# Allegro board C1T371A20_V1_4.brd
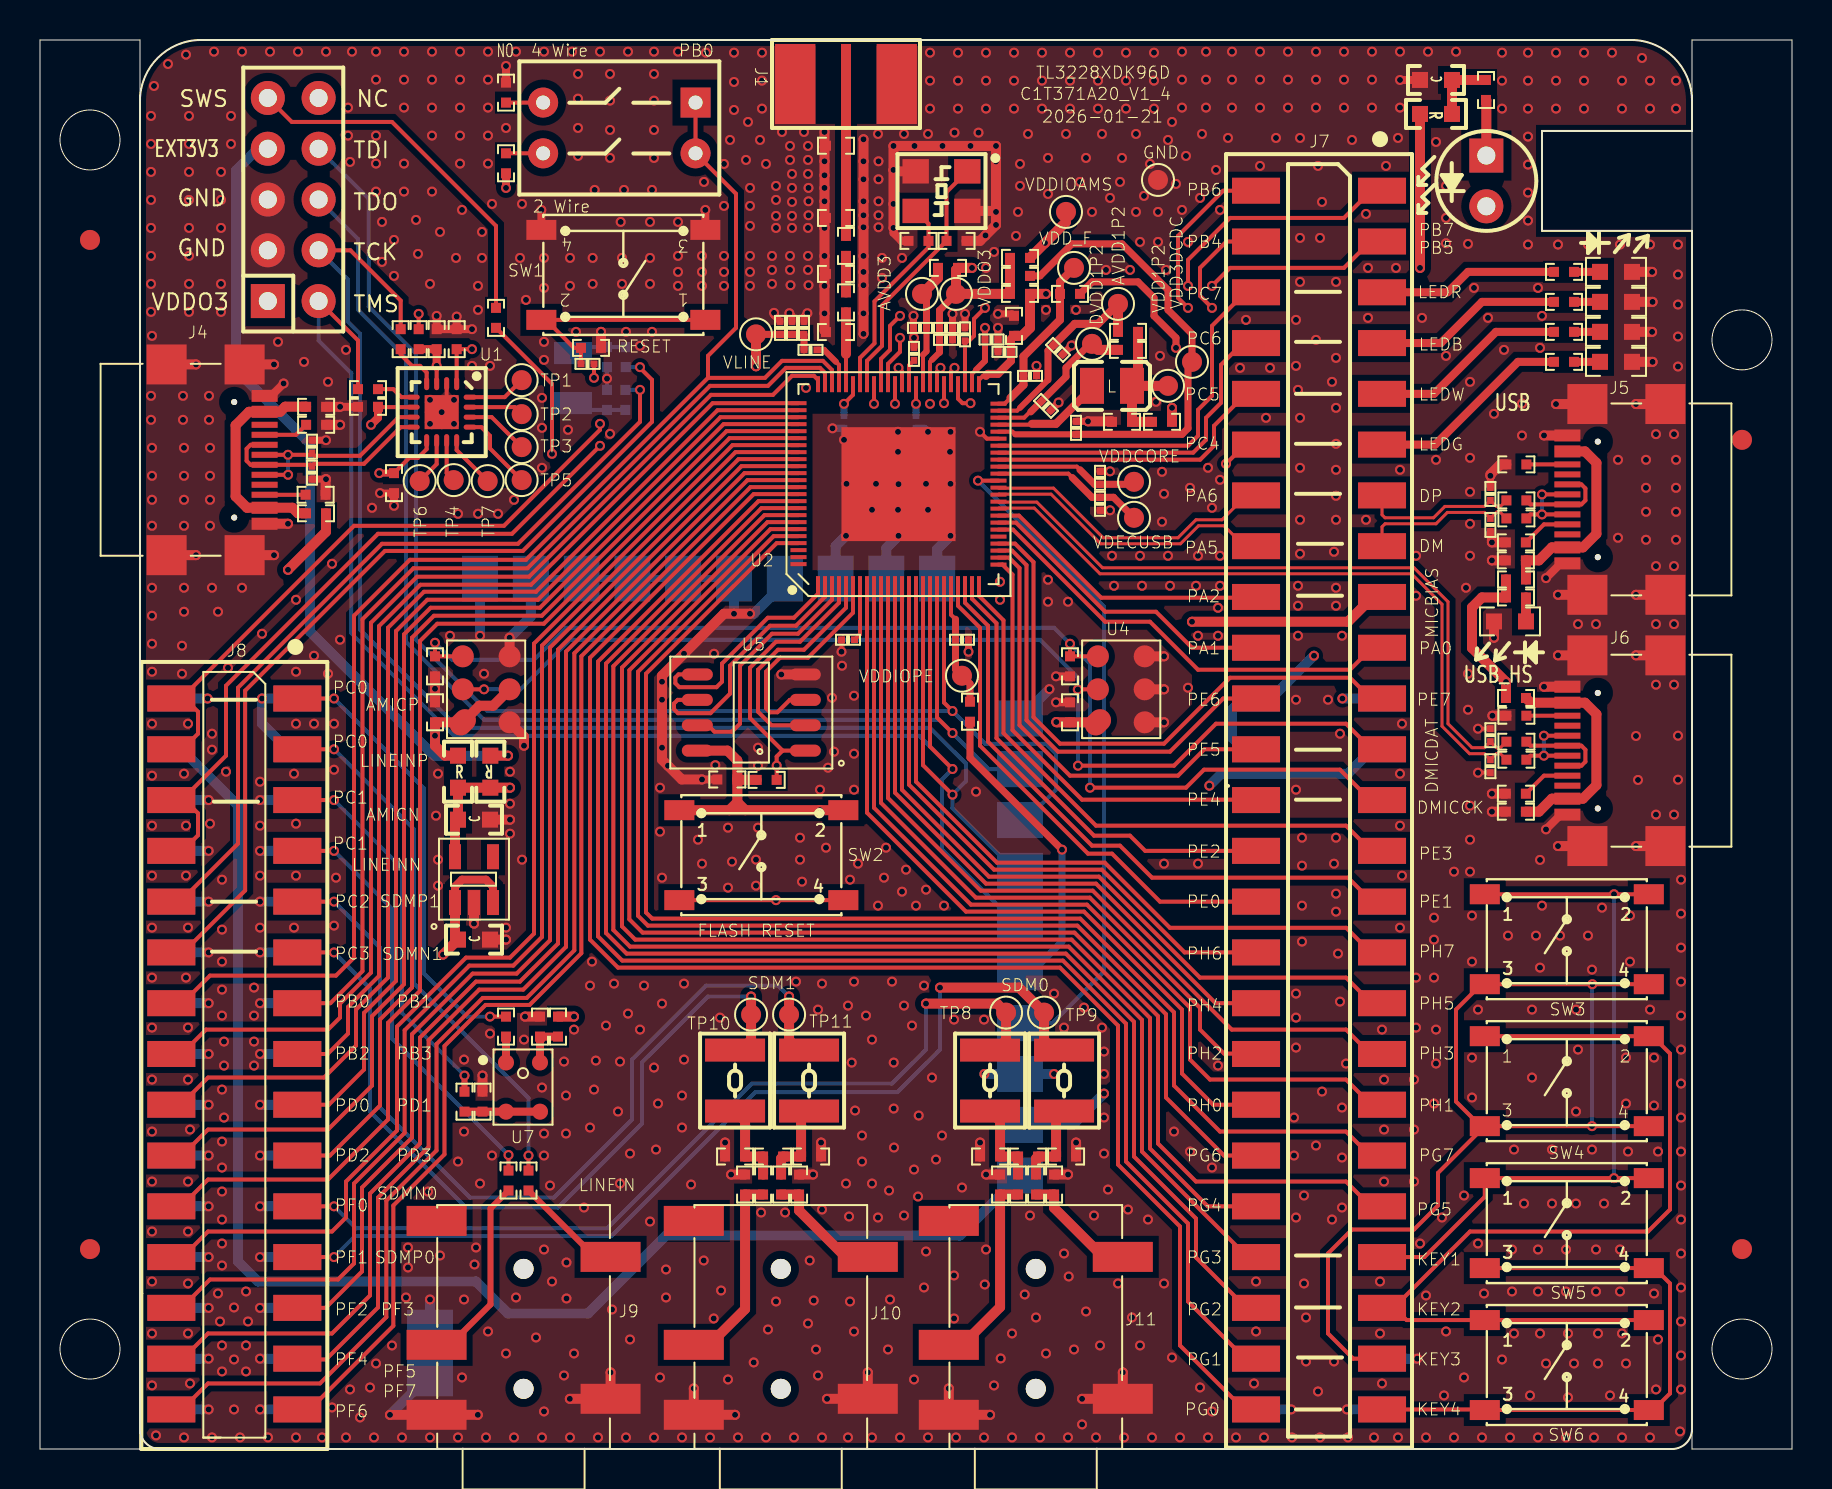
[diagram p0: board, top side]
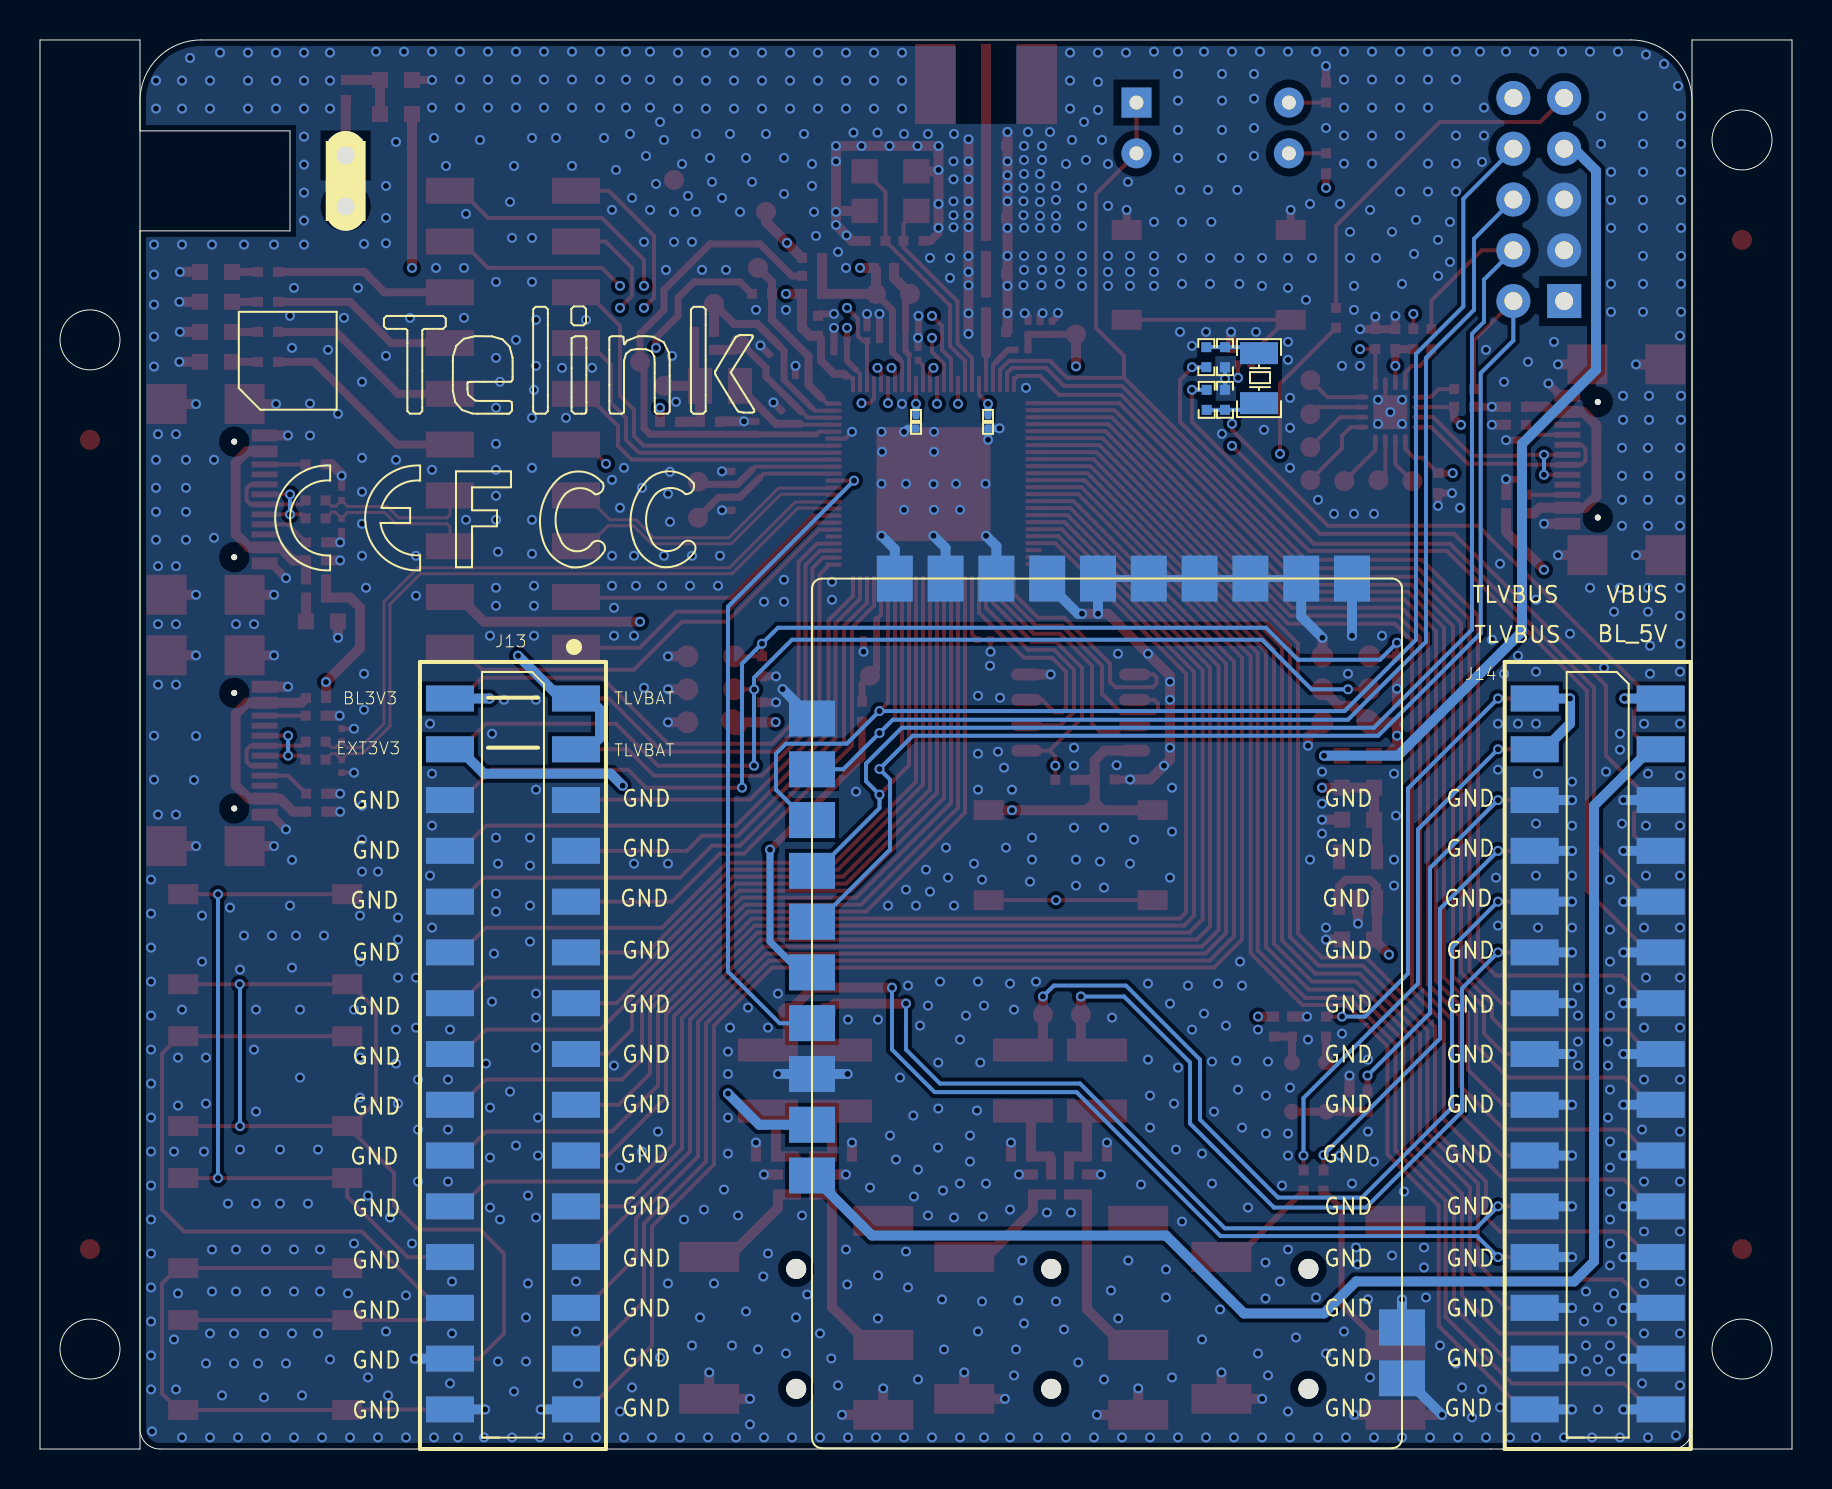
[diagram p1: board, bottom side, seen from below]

Outline 87.6 x 70.48 mm; copper layers: TOP, GND, POWER, BOTTOM. Coordinates in mm from the lower left corner of the outline.
Outline path: circle c2.5,65.48 r1.5 ; circle c2.5,5 r1.5 ; circle c85.1,55.48 r1.5 ; circle c85.1,5 r1.5 ; 0,70.48 5,70.48 5,0 0,0 0,70.48 ; 5,67.43 5,1 arc(5.29,0.29) 6,0 81.6,0 arc(82.31,0.29) 82.6,1 82.6,60.93 75.1,60.93 75.1,65.93 82.6,65.93 82.6,67.43 arc(81.71,69.59) 79.55,70.48 8.05,70.48 arc(5.89,69.59) 5,67.43 ; 82.6,70.48 87.6,70.48 87.6,0 82.6,0 82.6,70.48

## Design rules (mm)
net group DP1: nets TL_DM TL_DP
net group DP2: nets TL_PA3 TL_PA4
net group DP3: nets TL_PA5 TL_PA6
net group MG1: nets TL_MSPICK TL_MSPIIO2 TL_MSPIIO3 TL_MSPIMISO TL_MSPIMOSI

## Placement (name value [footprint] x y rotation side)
AVDD1P2  TP  [TP100]  53.9 57.28 0 top
AVDD3  TP  [TP100]  44.1 57.78 0 top
C1  10uF  [0603C]  69.8 68.48 0 top
C2  1.5pF  [0402]  39.8 61.58 0 top
C3  NC  [0402]  28.35 54.62 90 bottom
C4  NC  [0402]  28.35 52.48 270 bottom
C5  2.7pF  [0402]  39.8 58.78 0 top
C6  NC  [0402]  43.93 60.43 0 top
C7  NC  [0402]  45.83 60.43 180 top
C8  1.2pF  [0402]  39.8 55.87 0 top
C9  1uF  [0402]  27.55 55.08 0 top
C10  1uF  [0201]  43.7 54.78 90 top
C11  1uF  [0201]  44 56.08 180 top
C12  1uF  [0201]  45.3 56.08 0 top
C13  1uF  [0201]  47.58 55.5 0 top
C14  10uF  [0402]  48.7 56.18 90 top
C15  1uF  [0201]  49.5 53.68 0 top
C16  2.2uF  [0201]  37 56.08 90 top
C17  0.1uF  [0201]  37.6 56.08 90 top
C18  1uF  [0201]  50.9 54.98 315 top
C19  1uF  [0402]  19.83 55.51 90 top
C20  1uF  [0402]  20.83 55.51 90 top
C21  1uF  [0201]  50.3 52.18 315 top
C22  10uF  [0402]  54.1 51.38 180 top
C23  0.1uF  [0402]  16.4 52.13 180 top
C24  1uF  [0201]  51.8 51.08 90 top
C25  4.7uF  [0201]  53 48.58 90 top
C26  1uF  [0402]  17.7 48.31 270 top
C27  0.22uF  [0201]  53 47.28 270 top
C29  1uF  [0201]  40.4 40.48 180 top
C30  1uF  [0201]  46.1 40.48 0 top
C31  0.1uF  [0402]  19.75 36.85 90 top
C32  0.1uF  [0402]  51.5 36.85 90 top
C33  1uF  [0402]  34.37 33.49 180 top
C34  10uF  [0603C]  21.7 31.48 0 top
C35  10uF  [0603C]  21.7 25.48 0 top
C36  10nF  [0402]  23.3 21.13 90 top
C37  1uF  [0402]  25 21.13 90 top
C38  10nF  [0402]  21.22 17.38 90 top
C39  NC  [0402]  34.75 14.63 0 top
C40  220nF  [0402]  36.65 14.63 0 top
C41  NC  [0402]  38.55 14.63 0 top
C42  NC  [0402]  47.5 14.63 0 top
C43  220nF  [0402]  49.4 14.63 0 top
C44  NC  [0402]  51.3 14.63 0 top
C45  1uF  [0402]  23.43 13.43 90 top
C46  1uF  [0402]  24.43 13.43 90 top
C47  10pF  [0402]  35.25 13.23 270 top
C48  10pF  [0402]  37.95 13.23 90 top
C49  10pF  [0402]  48 13.23 270 top
C50  10pF  [0402]  50.7 13.23 90 top
C51  3.9pF  [0201]  38.2 56.08 90 top
C52  NC/3.9pF  [0201]  40.2 51.38 270 bottom
C53  3.9pF  [0201]  45.3 55.48 0 top
C56  3.9pF  [0201]  48.22 54.88 180 top
C61  NC/1uF  [0201]  43.8 51.38 270 bottom
C65  3.9pF  [0201]  46.25 55.76 90 top
D1  TT0321  [0402]  39.8 65.19 0 top
D2  LED_IR  [LED_TH_2P54MM_2PIN]  72.32 63.43 90 top
D3  Red  [0603-LED]  78.8 58.88 0 top
D4  Blue  [0603-LED]  78.8 57.38 0 top
D5  White  [0603-LED]  78.8 55.88 0 top
D6  Green  [0603-LED]  78.8 54.38 0 top
D7  NC  [0402]  13.81 52.13 180 top
D8  NC  [0201]  13.6 50.14 270 top
D9  NC  [0201]  13.6 48.84 90 top
D10  NC  [0201]  72.52 47.77 270 top
D11  NC  [0201]  72.52 46.22 90 top
D12  NC  [0402]  73.79 44.45 0 top
D13  Green  [0603-LED]  73.5 41.4 180 top
D14  NC  [0201]  72.52 35.71 270 top
D15  NC  [0201]  72.52 34.16 90 top
D16  NC  [0402]  73.79 31.88 0 top
DVDD1P2  TP  [TP100]  52.6 55.28 0 top
GND  TP  [TP100]  55.9 63.48 0 top
J1  RFIN  [SMA-H]  40.3 68.28 270 top
J2  DIP_2X2  [DIPSWITCH_2P54_7P62_2X2]  28.97 66.08 90 top
J3  JTAG  [HDR254F-2X5X850]  11.39 67.58 270 top
J4  Type-C 16pin  [TYPE_C_CQ_105PWB]  10.23 49.48 270 top
J5  Type-C 16pin  [TYPE_C_CQ_105PWB]  77.37 47.5 90 top
J6  Type-C 16pin  [TYPE_C_CQ_105PWB]  77.37 34.93 90 top
J7  HEADER 25X2  [HDR2X25-2R54-SM-M]  63.95 32.42 90 top
J8  HEADER 17X2  [SMD254M-2X15_RX1_30Y2_40]  9.72 10.87 90 top
J9  AIL1  [PJ-327]  24.18 0.01 180 top
J10  PJ327  [PJ-327]  37.04 0.01 180 top
J11  PJ327  [PJ-327]  49.79 0.01 180 top
J12  CON22  [ML_HDR254F-2X10X850]  49 13.68 90 bottom
J13  HEADER 17X2  [SMD254M-2X15_RX1_30Y2_40]  63.95 10.87 90 bottom
J14  HEADER 17X2  [SMD254M-2X15_RX1_30Y2_40]  9.72 10.87 90 bottom
L1  1.5nH  [0402]  40.3 60.18 90 top
L2  2.4nH  [0402]  40.3 57.36 90 top
L3  BEAD_600  [0402]  18.93 55.51 90 top
L4  6.8uH  [0806L]  53.6 53.18 0 top
L5  150uH  [INDM3025X25]  34.75 18.43 270 top
L6  150uH  [INDM3025X25]  38.45 18.43 270 top
L7  150uH  [INDM3025X25]  47.5 18.43 270 top
L8  150uH  [INDM3025X25]  51.2 18.43 270 top
L9  0  [0201]  38.53 54.98 180 top
L11  0  [0201]  27.38 54.28 180 top
NOREF  -  [unnamed]  2.5 60.48 180 top
NOREF#2  -  [unnamed]  85.1 50.48 180 top
NOREF#3  -  [unnamed]  85.1 10 0 top
NOREF#4  -  [unnamed]  2.5 10 0 top
R1  0  [0402]  22.8 56.58 270 top
R2  1R  [0402]  72.3 67.98 270 top
R3  1M  [0402]  23.3 67.85 90 top
R4  0R  [0603R]  69.8 66.78 180 top
R5  1K  [0402]  23.3 64.31 270 top
R6  NC  [0402]  29.27 52.48 90 bottom
R7  NC  [0402]  29.28 54.62 270 bottom
R8  1K  [0402]  76.2 58.88 0 top
R9  1K  [0402]  76.2 57.38 0 top
R10  1K  [0402]  76.2 55.88 0 top
R11  0R  [0402]  18.03 55.51 90 top
R12  1K  [0402]  76.2 54.38 0 top
R13  0R  [0402]  16.4 53.01 180 top
R14  5.1K  [0402]  13.81 51.23 180 top
R15  5.1K  [0402]  73.82 49.25 0 top
R16  5.1K  [0402]  13.78 47.73 180 top
R17  33  [0402]  73.82 47.45 180 top
R18  2R  [0402]  13.8 46.81 180 top
R19  33  [0402]  73.82 46.55 180 top
R20  5.1K  [0402]  73.79 45.35 0 top
R21  2R  [0402]  73.8 43.5 0 top
R22  10K  [0402]  73.8 42.6 180 top
R23  100K  [0402]  19.75 39.15 90 top
R24  100K  [0402]  51.5 39.15 90 top
R25  2R  [0402]  73.8 37.57 0 top
R26  5.1K  [0402]  73.82 36.68 0 top
R27  0  [0402]  73.82 35.38 180 top
R28  0  [0402]  73.82 34.48 180 top
R29  0R  [0603R]  20.9 33.88 270 top
R30  0R  [0603R]  22.52 33.88 90 top
R31  4.7K  [0402]  36.33 33.47 0 top
R32  5.1K  [0402]  73.79 32.78 0 top
R33  2.2K  [0402]  25.9 21.13 270 top
R34  2.2K  [0402]  22.12 17.38 270 top
R35  33  [0402R]  36.15 13.23 270 top
R36  33  [0402R]  37.05 13.23 270 top
R37  33  [0402R]  48.9 13.23 270 top
R38  33  [0402R]  49.8 13.23 270 top
R39  0  [0402R]  54.4 54.98 180 top
R40  0  [0402R]  54.4 55.88 180 top
R41  0  [0402R]  56.1 51.38 0 top
R42  0  [0402R]  49 59.58 0 top
R43  0  [0402R]  45.4 59.08 180 top
R44  0  [0402R]  49 58.68 0 top
R45  0  [0402R]  46.5 36.88 90 top
R46  0  [0402R]  51.5 57.78 0 top
R47  NC  [0402R]  49 57.78 0 top
SW1  SW4PIN_4.5x4.5  [SW_6X6_SMD]  29.17 58.73 180 top
SW2  FRST  [SW_6X6_SMD]  36.07 29.7 0 top
SW3  SW4PIN_4.5x4.5  [SW_6X6_SMD]  76.34 25.5 0 top
SW4  SW4PIN_4.5x4.5  [SW_6X6_SMD]  76.34 18.4 0 top
SW5  SW4PIN_4.5x4.5  [SW_6X6_SMD]  76.34 11.3 0 top
SW6  SW4PIN_4.5x4.5  [SW_6X6_SMD]  76.34 4.2 0 top
TP1  TP  [TP100]  24.08 53.46 270 top
TP2  TP  [TP100]  24.08 51.76 270 top
TP3  TP  [TP100]  24.08 50.11 270 top
TP4  TP  [TP100]  20.68 48.46 270 top
TP5  TP  [TP100]  24.08 48.46 270 top
TP6  TP  [TP100]  18.98 48.41 270 top
TP7  TP  [TP100]  22.38 48.41 270 top
TP8  B0  [TP100]  48.3 21.83 0 top
TP9  B1  [TP100]  50.2 21.83 0 top
TP10  D4  [TP100]  35.55 21.73 0 top
TP11  D5  [TP100]  37.45 21.73 0 top
U1  CH343P  [QFN_3X3_16PIN_0P5_1P70X1P70]  20.08 51.86 270 top
U2  TL3228X  [QFN_10X10_96PIN_0P35_5P7X5P7]  42.93 48.26 90 top
U3  WMM7047DTFN0  [DMIC_SPM0423HM4H-WB]  22.31 38 90 top
U4  WMM7047DTFN0  [DMIC_SPM0423HM4H-WB]  54.07 38 90 top
U5  P25Q32SU-SSH-IT  [W25X10_20_40BL]  35.57 36.84 90 top
U6  CE1132_3.3V_SOT-23-5  [SOT-23-5]  21.7 28.48 0 top
U7  WMM7037AT2  [GA_BFA423_A83]  24.15 18.11 0 top
VDD1P2  TP  [TP100]  56.4 53.18 0 top
VDD3DCDC  TP  [TP100]  57.6 54.38 0 top
VDD_F  TP  [TP100]  51.7 59.08 0 top
VDDCORE  TP  [TP100]  54.7 48.38 0 top
VDDIOAMS  TP  [TP100]  51.3 61.88 0 top
VDDIOPE  TP  [TP100]  46.1 38.68 0 top
VDDO3  TP  [TP100]  45.8 57.78 0 top
VDECUSB  TP  [TP100]  54.7 46.58 0 top
VLINE  TP  [TP100]  35.8 55.76 0 top
Y1  NC  [OSC-ABS07]  26.65 53.57 270 bottom
Y2  24MHz-12pF-+/-10ppm  [OSCCC250X320X110]  45.08 62.92 270 top

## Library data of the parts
AVDD1P2 AVDD3 DVDD1P2 GND TP1-TP11 VDD1P2 VDD3DCDC VDD_F VDDCORE VDDIOAMS VDDIOPE VDDO3 VDECUSB VLINE = TestPad100
C1 C9 C14 C22 C33 C36-C38 C45 C46 = C1005X5R1C104K
C2-C5 C8 = C1608_NC
C6 C7 C19 C20 C23 C26 C39 C41 C42 C44 = C1005_NC
C10-C13 C15-C18 C21 C24 C25 C27 C29 C30 C51-C53 C56 C61 C65 = C1005X5R1C104K: User Part Number: pn; Tolerance: RichardLC
C31 C32 = C1005X5R1C104K_1
C34 C35 = C1608X5R0J106M
C40 C43 = C1005X5R1C224M
C47-C50 = C1005C0G1H100D
D1 D7 D12 D16 = DIODE SCHOTTKY_0
D2 = Led_Th_3mm_1: User Part Number: partnum; Tolerance: RichardLC
D3-D6 D13 = 0603D_Green
D8-D11 D14 D15 = DIODE SCHOTTKY_0: User Part Number: pn; Tolerance: RichardLC
J1 = SMA_JACK_2
J2 = HEADER 2X2_0: Tolerance: RichardLC; User Part Number: pn
J3 = CONN PLUG 5x2: Tolerance: RichardLC; User Part Number: pn
J4-J6 = Type-C 16pin_0
J7 = HEADER 16X2_9: Tolerance: RichardLC
J8 J13 J14 = HEADER 16X2_13: Tolerance: RichardLC
J9-J11 = PJ327_2
J12 = CON24B_0: User Part Number: pn; Tolerance: RichardLC
L1 L2 = MLK1608_000R
L3 = MMZ1005Y601C
L4 = IND
L5-L8 = IND_150uH_3025
L9 L11 = MLK1608_000R: User Part Number: pn; Tolerance: RichardLC
R1 R3-R5 R23 R24 R29-R31 R33 R34 = RS0402K104JT
R2 R11 R13 R22 = RS0402K102JT
R6 R7 = RS0603K102JT
R8-R10 R12 = RS0402K101JT
R14-R21 R25-R28 R32 = RS0402K330JT: room: USB
R35-R47 = RS0402K330JT
SW1 SW3-SW6 = SW_6X6_SMD_0
SW2 = SW_6X6_SMD
U1 = CH343P
U2 = TL3228X_QFN96: Tolerance: RichardLC; User Part Number: pn
U3 = LD1117/SO_1
U4 = LD1117/SO_0
U5 = GD25LD40C_0: Tolerance: RichardLC
U6 = CE1132_1V8_SOT-23-5
U7 = MULPS4CX-RM5_0
Y1 = OSC_2x6_2pin_16Mhz
Y2 = CRYSTAL4/SM_0

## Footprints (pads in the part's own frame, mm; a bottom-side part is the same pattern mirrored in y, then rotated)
0201
  rect 0.35x0.33 smd: 1(-0.325,0) 2(0.325,0)
0402
  rect 0.5x0.5 smd: 1(-0.5,0) 2(0.5,0)
0402R
  rect 0.5x0.5 smd: 1(-0.5,0) 2(0.5,0)
0603-LED
  rect 0.8x0.8 smd: A(-0.8,0) C(0.8,0)
0603C
  rect 0.8x0.8 smd: 1(-0.8,0) 2(0.8,0)
0603R
  rect 0.8x0.8 smd: 1(-0.8,0) 2(0.8,0)
0806L
  rect 1.2x1.8 smd: 1(-1,0) 2(1,0)
DIPSWITCH_2P54_7P62_2X2
  rect 1.5x1.5 hole 0.7: 1(1.27,-3.81)
  round 1.5 hole 0.7: 2(1.27,3.81) 3(-1.27,-3.81) 4(-1.27,3.81)
DMIC_SPM0423HM4H-WB
  round 1.1 smd: 1(-1.65,-1.17) 2(0,-1.17) 3(1.65,-1.17) 4(1.65,1.17) 5(0,1.17)
  oval 1.4x1.1 smd rot 135: 6(-1.65,1.17)
GA_BFA423_A83
  round 0.8 smd: 1(-0.85,1.23) 2(-0.85,-1.23) 3(0.85,-1.23) 4(0.85,1.23)
HDR2X25-2R54-SM-M
  rect 1.3x2.4 smd: 1(30.52,-3.15) 2(30.52,3.15) 3(27.98,-3.15) 4(27.98,3.15) 5(25.44,-3.15) 6(25.44,3.15) 7(22.9,-3.15) 8(22.9,3.15) 9(20.36,-3.15) 10(20.36,3.15) 11(17.82,-3.15) 12(17.82,3.15) 13(15.28,-3.15) 14(15.28,3.15) 15(12.74,-3.15) 16(12.74,3.15) 17(10.2,-3.15) 18(10.2,3.15) 19(7.66,-3.15) 20(7.66,3.15) 21(5.12,-3.15) 22(5.12,3.15) 23(2.58,-3.15) 24(2.58,3.15) 25(0.04,-3.15) 26(0.04,3.15) 27(-2.5,-3.15) 28(-2.5,3.15) 29(-5.04,-3.15) 30(-5.04,3.15) 31(-7.58,-3.15) 32(-7.58,3.15) 33(-10.12,-3.15) 34(-10.12,3.15) 35(-12.66,-3.15) 36(-12.66,3.15) 37(-15.2,-3.15) 38(-15.2,3.15) 39(-17.74,-3.15) 40(-17.74,3.15) 41(-20.28,-3.15) 42(-20.28,3.15) 43(-22.82,-3.15) 44(-22.82,3.15) 45(-25.36,-3.15) 46(-25.36,3.15) 47(-27.9,-3.15) 48(-27.9,3.15) 49(-30.44,-3.15) 50(-30.44,3.15)
HDR254F-2X5X850
  rect 1.7x1.7 hole 0.9: 1(10.16,0)
  round 1.7 hole 0.9: 2(10.16,2.54) 3(7.62,0) 4(7.62,2.54) 5(5.08,0) 6(5.08,2.54) 7(2.54,0) 8(2.54,2.54) 9(0,0) 10(0,2.54)
INDM3025X25
  rect 1.15x3 smd: 1(-1.525,0) 2(1.525,0)
LED_TH_2P54MM_2PIN
  rect 1.7x1.7 hole 0.9: A(1.27,0)
  round 1.7 hole 0.9: C(-1.27,0)
ML_HDR254F-2X10X850
  rect 1.8x2.3 smd: 1(22.86,0) 2(20.32,0) 3(17.78,0) 4(15.24,0) 5(12.7,0) 6(10.16,0) 7(7.62,0) 8(5.08,0) 9(2.54,0) 10(0,0) 11(-10.14,-29.5) 12(-7.6,-29.5)
  rect 2.3x1.8 smd: 13(29.86,-27) 14(29.86,-24.46) 15(29.86,-21.92) 16(29.86,-19.38) 17(29.86,-16.84) 18(29.86,-14.3) 19(29.86,-11.76) 20(29.86,-9.22) 21(29.86,-6.68) 22(29.86,-4.14)
OSC-ABS07
  rect 1.1x1.9 smd: 1(-1.25,0) 2(1.25,0)
OSCCC250X320X110
  rect 1.22x1.32 smd: 1(-0.991,1.29) 2(-0.991,-1.29) 3(0.991,-1.29) 4(0.991,1.29)
PJ-327
  round 1 hole 1 unplated: (0,-3) (0,-9)
  rect 3x1.5 smd: 1(-4.35,-2.5) 2(4.35,-5.2) 3(-4.35,-9.6) 4(4.35,-11.4) 5(4.35,-1.7)
QFN_3X3_16PIN_0P5_1P70X1P70
  oval 0.65x0.25 smd: 1(-1.425,0.75) 2(-1.425,0.25) 3(-1.425,-0.25) 4(-1.425,-0.75) 9(1.425,-0.75) 10(1.425,-0.25) 11(1.425,0.25) 12(1.425,0.75)
  oval 0.25x0.65 smd: 5(-0.75,-1.425) 6(-0.25,-1.425) 7(0.25,-1.425) 8(0.75,-1.425) 13(0.75,1.425) 14(0.25,1.425) 15(-0.25,1.425) 16(-0.75,1.425)
  rect 1.7x1.7 smd: 17(0,0)
QFN_10X10_96PIN_0P35_5P7X5P7
  rect 0.8x0.2 smd: 1(-5,4.025) 2(-5,3.675) 3(-5,3.325) 4(-5,2.975) 5(-5,2.625) 6(-5,2.275) 7(-5,1.925) 8(-5,1.575) 9(-5,1.225) 10(-5,0.875) 11(-5,0.525) 12(-5,0.175) 13(-5,-0.175) 14(-5,-0.525) 15(-5,-0.875) 16(-5,-1.225) 17(-5,-1.575) 18(-5,-1.925) 19(-5,-2.275) 20(-5,-2.625) 21(-5,-2.975) 22(-5,-3.325) 23(-5,-3.675) 24(-5,-4.025) 49(5,-4.025) 50(5,-3.675) 51(5,-3.325) 52(5,-2.975) 53(5,-2.625) 54(5,-2.275) 55(5,-1.925) 56(5,-1.575) 57(5,-1.225) 58(5,-0.875) 59(5,-0.525) 60(5,-0.175) 61(5,0.175) 62(5,0.525) 63(5,0.875) 64(5,1.225) 65(5,1.575) 66(5,1.925) 67(5,2.275) 68(5,2.625) 69(5,2.975) 70(5,3.325) 71(5,3.675) 72(5,4.025)
  rect 0.2x0.8 smd: 25(-4.025,-5) 26(-3.675,-5) 27(-3.325,-5) 28(-2.975,-5) 29(-2.625,-5) 30(-2.275,-5) 31(-1.925,-5) 32(-1.575,-5) 33(-1.225,-5) 34(-0.875,-5) 35(-0.525,-5) 36(-0.175,-5) 37(0.175,-5) 38(0.525,-5) 39(0.875,-5) 40(1.225,-5) 41(1.575,-5) 42(1.925,-5) 43(2.275,-5) 44(2.625,-5) 45(2.975,-5) 46(3.325,-5) 47(3.675,-5) 48(4.025,-5) 73(4.05,5) 74(3.7,5) 75(3.35,5) 76(3,5) 77(2.65,5) 78(2.3,5) 79(1.95,5) 80(1.6,5) 81(1.25,5) 82(0.9,5) 83(0.55,5) 84(0.2,5) 85(-0.15,5) 86(-0.5,5) 87(-0.85,5) 88(-1.2,5) 89(-1.55,5) 90(-1.9,5) 91(-2.25,5) 92(-2.6,5) 93(-2.95,5) 94(-3.3,5) 95(-3.65,5) 96(-4,5)
  rect 5.7x5.7 smd: 97(0,0)
SMA-H
  rect 4x0.5 smd: 1(0,0)
  rect 4x2 smd: 2(0,-2.54) 3(0,2.54) 4(0,-2.54) 5(0,2.54)
SMD254M-2X15_RX1_30Y2_40
  rect 1.3x2.4 smd: 1(26.67,-3.15) 2(26.67,3.15) 3(24.13,-3.15) 4(24.13,3.15) 5(21.59,-3.15) 6(21.59,3.15) 7(19.05,-3.15) 8(19.05,3.15) 9(16.51,-3.15) 10(16.51,3.15) 11(13.97,-3.15) 12(13.97,3.15) 13(11.43,-3.15) 14(11.43,3.15) 15(8.89,-3.15) 16(8.89,3.15) 17(6.35,-3.15) 18(6.35,3.15) 19(3.81,-3.15) 20(3.81,3.15) 21(1.27,-3.15) 22(1.27,3.15) 23(-1.27,-3.15) 24(-1.27,3.15) 25(-3.81,-3.15) 26(-3.81,3.15) 27(-6.35,-3.15) 28(-6.35,3.15) 29(-8.89,-3.15) 30(-8.89,3.15)
SOT-23-5
  rect 0.6x1.25 smd: 1(-0.95,-1.145) 2(0,-1.145) 3(0.95,-1.145) 4(0.95,1.145) 5(-0.95,1.145)
SW_6X6_SMD
  rect 1.5x1 smd: 1(-4.1,2.25) 2(4.1,2.25) 3(-4.1,-2.25) 4(4.1,-2.25)
TP100
  round 1 smd: 1(0,0)
TYPE_C_CQ_105PWB
  round 0.3 hole 0.7 unplated: (-2.89,-0.52) (2.89,-0.52)
  rect 2x2 smd: 13(-4.77,0) 14(4.77,0) 15(-4.77,-3.9) 16(4.77,-3.9)
  rect 0.6x1.3 smd: A1B12(-3.2,1) A4B9(-2.4,1) B1A12(3.2,1) B4A9(2.4,1)
  rect 0.3x1.3 smd: A5(-1.25,1) A6(-0.25,1) A7(0.25,1) A8(1.25,1) B5(1.75,1) B6(0.75,1) B7(-0.75,1) B8(-1.75,1)
unnamed
  round 1 smd: 1(0,0)
W25X10_20_40BL
  oval 0.6x1.55 smd: 1(-1.905,-2.7) 2(-0.635,-2.7) 3(0.635,-2.7) 4(1.905,-2.7) 5(1.905,2.7) 6(0.635,2.7) 7(-0.635,2.7) 8(-1.905,2.7)

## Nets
GND: C1.1 C2.1 C3.1 C4.1 C5.1 C6.1 C7.1 C8.1 C9.2 C10.2 C11.2 C12.2 C13.2 C14.2 C15.2 C16.2 C17.2 C18.2 C19.2 C20.2 C21.2 C22.2 C23.2 C24.2 C25.2 C26.2 C27.2 C29.2 C30.2 C31.2 C32.2 C33.2 C34.2 C35.2 C37.2 C39.1 C41.2 C42.1 C44.2 C47.1 C48.2 C49.1 C50.2 C51.2 C52.2 C53.2 C56.2 C61.2 C65.2 D1.1(ANODE) D3.C(CATHODE) D4.C(CATHODE) D5.C(CATHODE) D6.C(CATHODE) D7.1(ANODE) D8.1(ANODE) D9.1(ANODE) D10.1(ANODE) D11.1(ANODE) D12.1(ANODE) D13.C(CATHODE) D14.1(ANODE) D15.1(ANODE) D16.1(ANODE) GND.1(TP) J1.2 J1.3 J1.4 J1.5 J3.3(7) J3.5 J4.13(GND#13) J4.14(GND#14) J4.15(GND#15) J4.16(GND#16) J4.A1B12(GND#A1B12) J4.B1A12(GND#B1A12) J5.13(GND#13) J5.14(GND#14) J5.15(GND#15) J5.16(GND#16) J5.A1B12(GND#A1B12) J5.B1A12(GND#B1A12) J6.13(GND#13) J6.14(GND#14) J6.15(GND#15) J6.16(GND#16) J6.A1B12(GND#A1B12) J6.B1A12(GND#B1A12) J9.1 J9.5 J10.1 J10.5 J11.1 J11.5 J12.1 J12.8 J12.11 J12.12 J12.13 J12.14 J12.15 J12.16 J12.17 J12.18 J12.19 J12.20 J12.21 J12.22 J13.5 J13.6 J13.7 J13.8 J13.9 J13.10 J13.11 J13.12 J13.13 J13.14 J13.15 J13.16 J13.17 J13.18 J13.19 J13.20 J13.21 J13.22 J13.23 J13.24 J13.25 J13.26 J13.27 J13.28 J13.29 J13.30 J14.5 J14.6 J14.7 J14.8 J14.9 J14.10 J14.11 J14.12 J14.13 J14.14 J14.15 J14.16 J14.17 J14.18 J14.19 J14.20 J14.21 J14.22 J14.23 J14.24 J14.25 J14.26 J14.27 J14.28 J14.29 J14.30 R3.2 R14.1 R15.1 R16.1 R20.1 R23.1 R24.1 R26.1 R32.1 R34.1 SW1.3 SW1.4 U1.2(GND#2) U1.17(GND#17) U2.43(DVSS) U2.97(VSS) U3.1(GND1) U3.3(GND2) U4.1(GND1) U4.2(SE) U4.3(GND2) U5.4(VSS) U6.2(VSS) Y2.2 Y2.4
V3: C20.1 C23.1 U1.1(VIO) U1.6(V3)
VDD_DMIC: C31.1 C32.1 R29.1 U3.2(SE) U3.6(POWER) U4.6(POWER)
32K_XC1: J8.10 R6.2 U2.62(PC2)
32K_XC2: J8.12 R7.2 U2.63(PC3)
AIN_LINEIN_N: C45.2 J8.7
AIN_LINEIN_P: C46.2 J8.3
AIN_MIC_N: C38.2 J8.5
AIN_MIC_P: C36.2 J8.1
BL_3V3: J12.9 J13.2
BL_5V: J12.10 J14.3
DM0: J6.A7(DM1) J6.B7(DM2) R27.1
DM1: J5.A7(DM1) J5.B7(DM2) R19.1
DM2: D9.2(CATHODE) J4.A7(DM1) J4.B7(DM2) U1.8(VD-)
DMICCK: J7.25 R23.2 R24.2 U3.4(CLOCK) U4.4(CLOCK)
DMICDAT: J7.23 U3.5(DATA) U4.5(DATA)
DP0: J6.A6(DP1) J6.B6(DP2) R28.1
DP1: J5.A6(DP1) J5.B6(DP2) R17.1
DP2: D8.2(CATHODE) J4.A6(DP1) J4.B6(DP2) U1.7(VD+)
EXT_3V3: J3.7(3) J13.4 R30.2
LED_B: J7.7 R9.1
LED_G: J7.11 R12.1
LED_R: J7.5 R8.1
LED_W: J7.9 R10.1
TL_3V3C: C34.1 R4.2 R29.2 R30.1 U6.5(VOUT)
TL_5V: C35.1 J14.1 L3.2 R18.1 R21.1 R22.2 R25.1 U6.1(VIN) U6.3(CE)
TL_AVDD1P2: AVDD1P2.1(TP) C18.1 R40.2 U2.47(AVDD1P2)
TL_AVDD3: AVDD3.1(TP) C11.1 R43.2 U2.57(AVDD3)
TL_DM: D11.2(CATHODE) J7.15 R19.2
TL_DP: D10.2(CATHODE) J7.13 R17.2
TL_DVDD1P2: C21.1 DVDD1P2.1(TP) R39.2 U2.46(DVDD1P2)
TL_FLASH: C33.1 R31.1 R46.2 SW2.1 SW2.2 U5.8(VCC)
TL_IR: C65.1 D2.C(CATHODE) U2.51(IR)
TL_KEY1: J7.43 SW3.1 SW3.2 SW5.1 SW5.2
TL_KEY2: J7.45 SW4.1 SW4.2 SW6.1 SW6.2
TL_KEY3: J7.47 SW3.3 SW3.4 SW4.3 SW4.4
TL_KEY4: J7.49 SW5.3 SW5.4 SW6.3 SW6.4
TL_MICBIAS: J7.17 R33.1
TL_MSPICK: U2.2(PI1) U5.6(SCLK)
TL_MSPICN: R31.2 SW2.3 SW2.4 U2.4(PI3) U5.1(C\S\)
TL_MSPIIO2: U2.6(PI5) U5.3(W\P\/IO2)
TL_MSPIIO3: U2.3(PI2) U5.7(HOLD/IO3)
TL_MSPIMISO: U2.5(PI4) U5.2(SO/IO1)
TL_MSPIMOSI: U2.1(PI0) U5.5(SI/IO0)
TL_PA0: J7.19 U2.30(PA0)
TL_PA1: J7.20 U2.31(PA1)
TL_PA2: J7.18 U2.32(PA2)
TL_PA3: D14.2(CATHODE) R27.2 U2.34(PA3)
TL_PA4: D15.2(CATHODE) R28.2 U2.33(PA4)
TL_PA5: J7.16 U2.35(PA5)
TL_PA6: J7.14 U2.36(PA6)
TL_PA7: J12.7 R1.2 U2.37(PA7)
TL_PB0: J2.1 J2.3 J8.14 U2.70(PB0)
TL_PB1: J8.13 U2.71(PB1)
TL_PB2: J8.16 U2.72(PB2)
TL_PB3: J8.15 U2.73(PB3)
TL_PB4: J7.4 U2.52(PB4)
TL_PB5: J7.3 U2.53(PB5)
TL_PB6: J7.2 U2.54(PB6)
TL_PB7: J7.1 U2.55(PB7)
TL_PC0: J8.2 J8.4 U2.60(PC0)
TL_PC1: J8.6 J8.8 U2.61(PC1)
TL_PC4: J7.12 U2.64(PC4)
TL_PC5: J7.10 U2.40(PC5)
TL_PC6: J7.8 U2.41(PC6)
TL_PC7: J7.6 U2.42(PC7)
TL_PD0: J8.18 U2.74(PD0)
TL_PD1: J8.17 U2.75(PD1)
TL_PD2: J8.20 U2.76(PD2)
TL_PD3: J8.19 U2.77(PD3)
TL_PD4: J3.8(4) J12.3 U2.19(PD4)
TL_PD5: J3.6 J12.2 U2.18(PD5)
TL_PD6: J3.2(10) J12.5 R13.2 U2.17(PD6)
TL_PD7: J3.4(8) J12.4 R11.2 U2.16(PD7)
TL_PE0: J7.30 U2.21(PE0)
TL_PE1: J7.29 U2.22(PE1)
TL_PE2: J7.28 U2.23(PE2)
TL_PE3: J7.27 U2.24(PE3)
TL_PE4: J7.26 U2.25(PE4)
TL_PE5: J7.24 U2.26(PE5)
TL_PE6: J7.22 U2.27(PE6)
TL_PE7: J7.21 U2.28(PE7)
TL_PF0: J8.22 U2.78(PF0)
TL_PF1: J8.24 U2.79(PF1)
TL_PF2: J8.26 U2.80(PF2)
TL_PF3: J8.25 U2.81(PF3)
TL_PF4: J8.28 U2.82(PF4)
TL_PF5: J8.27 U2.83(PF5)
TL_PF6: J8.30 U2.84(PF6)
TL_PF7: J8.29 U2.85(PF7)
TL_PG0: J7.50 U2.86(PG0)
TL_PG1: J7.48 U2.87(PG1)
TL_PG2: J7.46 U2.88(PG2)
TL_PG3: J7.44 U2.89(PG3)
TL_PG4: J7.42 U2.90(PG4)
TL_PG5: J7.41 U2.91(PG5)
TL_PG6: J7.40 U2.92(PG6)
TL_PG7: J7.39 U2.93(PG7)
TL_PH0: J7.38 U2.8(PH0)
TL_PH1: J7.37 U2.9(PH1)
TL_PH2: J7.36 U2.10(PH2)
TL_PH3: J7.35 U2.11(PH3)
TL_PH4: J7.34 U2.12(PH4)
TL_PH5: J7.33 U2.13(PH5)
TL_PH6: J7.32 U2.14(PH6)
TL_PH7: J7.31 U2.15(PH7)
TL_RST: C9.1 L11.2 SW1.1 SW1.2
TL_SDMN0: J8.21 L7.1 TP8.1(TP)
TL_SDMN1: J8.11 L5.1 TP10.1(TP)
TL_SDMP0: J8.23 L8.1 TP9.1(TP)
TL_SDMP1: J8.9 L6.1 TP11.1(TP)
TL_VBAT: C14.1 C56.1 J13.1 J13.3 R47.2 U2.49(VBAT)
TL_VBUS: C13.1 J14.2 J14.4 U2.50(VBUS)
TL_VDD1P2: C22.1 L4.2 R39.1 R40.1 R41.1 VDD1P2.1(TP)
TL_VDD3DCDC: C24.1 R44.2 U2.44(VDD3DCDC) VDD3DCDC.1(TP)
TL_VDD_IR: C1.2 R2.1 R4.1
TL_VDDCORE: C25.1 U2.39(VDDCORE) VDDCORE.1(TP)
TL_VDDIOAMS: C61.1 R42.2 U2.58(VDDIOAMS) VDDIOAMS.1(TP)
TL_VDDIOF: C15.1 R46.1 U2.48(VDDIOF) VDD_F.1(TP)
TL_VDDIOF1: C29.1 U2.7(VDDIOF1)
TL_VDDIOPE: C30.1 R45.2 U2.20(VDDIOPE) VDDIOPE.1(TP)
TL_VDDO3: C12.1 C53.1 J3.1(9) J12.6 R5.2 R42.1 R43.1 R44.1 R45.1 R47.1 U2.56(VDDO3) VDDO3.1(TP)
TL_VDECUSB: C27.1 U2.38(VDECUSB) VDECUSB.1(TP)
TL_VHHRRAM: U2.29(VHHRRAM)
TL_VLINE: C16.1 C17.1 C51.1 L9.2 R41.2 VLINE.1(TP)
TL_XC1: C7.2 U2.65(XC1) Y2.1
TL_XC2: C6.2 U2.66(XC2) Y2.3
UART_5V: C19.1 C26.1 L3.1 U1.3(VDD5) U1.9(VBUS)
UART_RX: R13.1 U1.5(RXD)
UART_TX: R11.1 U1.4(TXD)
USB_VBUSF: D12.2(CATHODE) J5.A4B9(VBUS#A4B9) J5.B4A9(VBUS#B4A9) R21.2
USB_VBUSH: D16.2(CATHODE) J6.A4B9(VBUS#A4B9) J6.B4A9(VBUS#B4A9) R25.2
USB_VBUSU: D7.2(CATHODE) J4.A4B9(VBUS#A4B9) J4.B4A9(VBUS#B4A9) R18.2
N20198704: C5.2 L1.1 L2.2
N20202485: C3.2 R7.1 Y1.1
N20202489: C4.2 R6.1 Y1.2
N20224092: C2.2 D1.2(CATHODE) J1.1 L1.2
N20257999: J5.A5(CC1) R20.2
N20258001: J5.B5(CC2) R15.2
N20274526: D2.A(ANODE) R2.2
N20306435: J6.A5(CC1) R32.2
N20306436: J6.B5(CC2) R26.2
N20337202: C39.2 C40.1 L5.2 R35.1
N20337204: C47.2 J10.2 R35.2
N20337251: C40.2 C41.1 L6.2 R36.1
N20337259: C48.1 J10.3 R36.2
N20337346: C42.2 C43.1 L7.2 R37.1
N20337363: C49.2 J11.2 R37.2
N20337410: C43.2 C44.1 L8.2 R38.1
N20337418: C50.1 J11.3 R38.2
N20381027: D13.A(ANODE) R22.1
N20392329: D3.A(ANODE) R8.2
N20392898: D4.A(ANODE) R9.2
N20393445: D5.A(ANODE) R10.2
N20393873: D6.A(ANODE) R12.2
N20430471: C8.2 L2.1 U2.68(ANT)
N20434720: C52.1 L11.1 U2.67(POR)
N20435400: L4.1 U2.45(DCDCSW)
N20464812: C36.1 U7.1(OUTPUT)
N20464818: C38.1 R34.2 U7.2(GND#2) U7.3(GND#3)
N20464835: C45.1 J9.2
N20464868: C46.1 J9.3
N20464905: C37.1 R33.2 U7.4(VDD)
N20480616: TP7.1(TP) U1.12(DTR)
N20480626: TP4.1(TP) U1.11(DCD)
N20480630: TP6.1(TP) U1.10(ACT#)
N20480671: TP5.1(TP) U1.13(RTS)
N20480690: TP3.1(TP) U1.14(DSR)
N20480706: TP2.1(TP) U1.15(CTS)
N20480721: TP1.1(TP) U1.16(RI)
N20480861: J4.A5(CC1) R14.2
N20480863: J4.B5(CC2) R16.2
N20516342: L9.1 U2.69(VLINE)
N20517911: C10.1 U2.59(VMID)
N202577100: J2.2 R3.1
N202577180: J2.4 R5.1
N204754409: J3.9(1) R1.1

Pads without a net: J3 10; J4 A8 B8; J5 A8 B8; J6 A8 B8; J9 4; J10 4; J11 4; NOREF 1; NOREF#2 1; NOREF#3 1; NOREF#4 1; U2 94 95 96; U6 4

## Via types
v1: diameter 0.5, hole 0.3, TOP to BOTTOM, 1289 vias

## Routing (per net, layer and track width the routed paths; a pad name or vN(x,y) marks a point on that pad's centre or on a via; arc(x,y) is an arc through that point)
GND: length 252.7
  TOP w0.2: C29.2 v1(40.08,39.88) ; v1(20.08,51.86) 20.33,52.11 U1.2 ; D15.1 v1(71.9,33.83) ; 39.22,65.12 D1.1 ; 39.22,61.58 C2.1 ; D14.1 v1(71.9,36.03) ; 39.22,58.78 C5.1 ; U2.43 47.34,50.54 v1(47,50.88)
  TOP w0.35: C14.2 48.6,56.78 v1(47.9,56.78) ; C53.2 C12.2 v1(45.62,56.78) ; 37.6,56.41 37.6,56.68 v1(37.47,56.81) ; D8.1 v1(14.3,50.46) ; v1(38.37,56.81) 38.2,56.64 38.2,56.41 ; v1(47.9,56.08) C13.2 C56.2 ; C26.2 v1(17,47.81) ; D9.1 v1(14.3,48.51) ; v1(36.7,56.83) 36.7,56.71 37,56.41 ; v1(43.68,56.68) C11.2 43.68,55.61 v1(43.7,55.58) C10.2 ; v1(72.59,45.35) 72.52,45.42 D11.1 ; v1(53.5,46.96) 53,46.96 ; v1(52.4,51.41) 51.8,51.41 ; C21.2 v1(50.93,52.35) ; v1(46.42,39.88) C30.2 ; v1(51.58,55.2) C18.2 ; C15.2 v1(49.83,54.18) ; v1(53.5,48.91) 53,48.91 ; D10.1 v1(72.52,48.68) ; C65.2 v1(46.25,56.78)
  TOP w0.4: R24.1 v1(50.8,38.65) ; SW1.4 v1(25.07,61.98) ; v1(42.68,61.08) 42.68,60.83 43.08,60.43 C6.1 ; J4.A1B12 11.56,52.68 v1(12.18,53.3) ; v1(75.3,43.56) 76.04,44.3 J5.A1B12 ; v1(33.1,33.49) C33.2 ; R3.2 v1(23.3,69.18) ; J6.A1B12 76.04,31.73 v1(75.3,30.99) ; C26.2 v1(17.7,47.18) ; v1(19.83,56.68) C19.2 C20.2 ; SW1.3 v1(33.27,61.98) ; C20.2 v1(21.6,56.01) ; C20.2 v1(20.83,56.65) ; C23.2 v1(15,52.13) ; C32.2 v1(50.8,37.35) ; C1.1 v1(68,68.48)
  TOP w0.5: v1(47.8,61.88) v1(47.8,64.41) v1(47.8,65.18) v1(46.53,65.18) v1(45.12,65.18) v1(43.72,65.18) v1(42.68,65.18) v1(42.68,63.98) ; v1(47.8,61.88) 47.75,61.93 Y2.4 ; v1(47.8,61.88) v1(47.8,61.23) v1(47.28,60.71) 47,60.43 C7.1 ; D13.C v1(72.7,40.58) ; C39.1 v1(34.25,15.33) ; C47.1 v1(34.55,13.73) ; v1(42.68,63.98) v1(42.68,62.28) v1(42.68,61.08) ; v1(42.68,63.98) 42.74,63.91 Y2.2 ; v1(52.1,2.51) J11.1 v1(54.14,3.83) ; C8.1 39.22,55.95 v1(39.22,56.8) v1(39.22,58.18) v1(39.22,59.68) v1(39.22,61.08) v1(39.22,62.41) v1(39.22,63.08) v1(39.22,63.71) v1(39.22,64.41) v1(39.22,65.88) ; D7.1 v1(15,52.13) ; J6.15 v1(79.8,30.16) ; D16.1 v1(72.59,31.88) ; v1(34.75,1.71) J10.5 v1(32.69,3.03) ; v1(17.5,1.71) J9.5 v1(21.89,1.71) ; C49.1 v1(47.3,13.73) ; C41.2 v1(39.05,15.33) ; J4.16 v1(7.8,44.71) ; C31.2 v1(19.75,38.03) R23.1 ; v1(80.6,55.88) D5.C ; v1(41.18,55.78) v1(41.18,56.8) v1(41.18,58.21) v1(41.18,58.88) v1(41.18,59.68) v1(41.18,61.11) v1(41.18,61.71) v1(41.18,62.41) v1(41.18,63.51) v1(41.18,64.41) v1(41.18,65.51) ; R14.1 v1(15,51.23) ; J6.16 v1(79.8,39.7) ; C22.2 53.58,51.41 v1(52.4,51.41) ; D12.1 v1(72.59,44.45) ; J6.13 v1(75.9,30.16) ; v1(28.53,3.83) J9.1 v1(26.49,2.51) ; C35.2 v1(23.3,25.48) ; R15.1 73.02,49.25 72.52,48.75 v1(72.52,48.68) ; J5.16 v1(79.8,52.27) ; v1(33.1,33.49) 32.09,33.49 v1(31.4,34.18) 31.1,34.48 v1(31.1,35.08) v1(31.1,37.48) v1(31.1,38.38) 31.1,38.68 v1(32.2,39.78) 34.2,41.78 v1(34.7,41.78) v1(35.5,41.78) ; J6.14 v1(75.9,39.7) ; U3.3 v1(23.48,40.58) ; U6.2 v1(21.7,26.28) ; v1(24.2,35.18) 24.2,35.63 U3.1 ; C48.2 v1(38.65,13.73) ; D3.C v1(80.6,58.88) ; C44.2 v1(51.8,15.33) ; J5.15 v1(79.8,42.73) ; v1(45.44,3.03) J11.5 v1(47.5,1.71) ; v1(80.63,57.38) D4.C ; R26.1 v1(72.62,36.68) ; C50.2 v1(51.4,13.73) ; R34.1 v1(22.12,18.68) ; C9.2 v1(28.05,55.88) ; R16.1 14.28,48.49 v1(14.3,48.51) ; C34.2 v1(23.5,31.48) ; J4.B1A12 v1(12.4,46.28) ; U5.4 v1(37.07,38.74) ; U4.3 v1(56.2,39.65) ; J4.13 v1(11.7,54.25) ; v1(41.39,3.83) J10.1 v1(39.35,2.51) ; R32.1 v1(72.59,32.78) ; v1(80.63,54.38) D6.C ; J4.14 v1(11.7,44.71) ; C37.2 v1(24.25,21.63) ; J4.15 v1(7.8,54.25) ; U4.2 v1(56.2,38) ; C42.1 v1(47,15.33) ; J5.13 v1(75.9,42.73) ; J5.14 v1(75.8,52.27) ; R20.1 v1(72.59,45.35) ; J6.B1A12 v1(75.2,38.13) ; U4.1 v1(56.2,36.35) ; J5.B1A12 v1(75.2,50.7)
  BOTTOM w0.2: C3.1 v1(28.35,53.54) C4.1
  BOTTOM w0.35: C61.2 44.22,51.05 v1(44.4,50.88) ; J12.14 J12.15 J12.16 J12.17 J12.18 ; v1(39.62,51.05) C52.2 v1(40.2,50.48)
  BOTTOM w0.5: J14.28 v1(11,4.52) ; J14.8 v1(11,29.92) ; J12.18 v1(34.7,41.78) ; v1(45.53,45.68) 44.86,45.02 J12.22 ; J12.14 24.54,41.64 v1(23.48,40.58) ; J14.20 v1(11,14.68) ; J14.16 v1(11,19.76) ; J14.6 v1(11,32.46) ; J14.17 v1(8.43,17.22) ; J14.27 v1(8.43,4.52) ; J12.12 v1(19.5,7.48) ; J14.24 v1(11,9.6) ; J14.19 v1(8.43,14.68) ; v1(42.93,45.68) 42.32,45.08 J12.21 ; J14.11 v1(8.43,24.84) ; J12.19 37.24,43.32 35.7,41.78 v1(35.5,41.78) ; J14.12 v1(11,24.84) ; J12.13 v1(22,40.68) ; J12.20 39.78,45.16 v1(40.3,45.68) ; J14.15 v1(8.43,19.76) ; J14.13 v1(8.43,22.3) ; J14.25 v1(8.43,7.06) ; v1(17.5,1.71) 19.33,3.54 J12.11 ; J14.10 v1(11,27.38) ; J14.9 v1(8.43,27.38) ; J14.22 v1(11,12.14) ; J14.5 v1(8.43,32.46) ; v1(47.22,18.76) J12.8 v1(50.7,18.76) ; J14.14 v1(11,22.3) ; J14.23 v1(8.43,9.6) ; J14.18 v1(11,17.22) ; J13.30 v1(65.34,1.98) ; J12.1 v1(50.47,38.01) ; J14.26 v1(11,7.06) ; J14.7 v1(8.43,29.92) ; J13.28 v1(68.86,4.52) ; J14.21 v1(8.43,12.14) ; J14.29 v1(8.43,1.98) ; J13.29 v1(62.56,1.98) ; J14.30 v1(11,1.98)
  vias: v1(5.55,66.68) v1(5.55,65.28) v1(5.55,63.88) v1(5.55,62.48) v1(5.55,61.08) v1(5.55,59.68) v1(5.55,58.28) v1(5.55,56.88) v1(5.6,55.68) v1(5.55,52.68) v1(5.55,51.48) v1(5.6,50.08) v1(5.6,48.68) v1(5.6,47.48) v1(5.6,46.18) v1(5.6,43.08) v1(5.6,41.68) v1(5.6,40.28) v1(5.6,38.88) v1(5.6,36.28) v1(5.6,33.68) v1(5.6,31.18) v1(5.6,28.68) v1(5.6,26.08) v1(5.6,23.58) v1(5.6,21.08) v1(5.6,18.48) v1(5.6,15.88) v1(5.6,13.38) v1(5.6,10.88) v1(5.6,8.38) v1(5.6,5.78) v1(5.6,3.18) v1(5.7,68.18) v1(5.8,0.68) v1(6.4,69.28) v1(7.15,52.68) v1(7.15,51.48) v1(7.1,40.18) v1(7.1,38.78) v1(7.2,50.08) v1(7.2,48.68) v1(7.2,47.48) v1(7.2,46.18) v1(7.2,43.08) v1(7.2,41.88) v1(7.2,33.78) v1(7.2,0.58) v1(7.3,69.75) v1(7.3,31.18) v1(7.3,28.68) v1(7.3,23.58) v1(7.4,36.28) v1(7.4,26.08) v1(7.4,21.08) v1(7.4,18.48) v1(7.4,13.38) v1(7.4,10.88) v1(7.4,8.28) v1(7.4,5.78) v1(7.45,66.68) v1(7.45,65.28) v1(7.45,63.88) v1(7.45,62.48) v1(7.45,61.08) v1(7.45,59.68) v1(7.45,58.28) v1(7.45,56.88) v1(7.5,15.98) v1(7.5,3.28) v1(8.45,52.68) v1(8.45,51.48) v1(8.5,50.08) v1(8.5,48.68) v1(8.5,47.48) v1(8.5,46.18) v1(8.5,31.28) v1(8.6,43.08) v1(8.6,35.78) v1(8.6,34.98) v1(8.6,0.58) v1(8.7,69.9) v1(8.9,41.88) v1(8.9,7.78) v1(9,6.38) v1(9.05,63.88) v1(9.05,62.48) v1(9.05,61.08) v1(9.05,58.28) v1(9.05,56.88) v1(9.1,28.48) v1(9.1,25.98) v1(9.1,24.38) v1(9.1,22.98) v1(9.1,21.68) v1(9.1,17.98) v1(9.1,15.38) v1(9.1,14.08) v1(9.1,12.88) v1(9.1,11.48) v1(9.1,10.28) v1(9.1,9.18) v1(9.1,5.18) v1(9.1,3.88) v1(9.2,20.38) v1(9.2,19.18) v1(9.2,16.58) v1(9.3,33.88) v1(9.4,39.08) v1(9.55,66.68) v1(9.55,65.28) v1(9.7,7.08) v1(9.7,4.48) v1(9.7,1.98) v1(10,0.58) v1(10.1,69.9) v1(10.1,43.08) v1(10.3,7.88) v1(10.3,5.18) v1(10.3,3.88) v1(10.4,6.38) v1(10.7,23.08) v1(10.7,21.68) v1(10.7,20.38) v1(10.7,19.18) v1(11,33.38) v1(11,31.18) v1(11,28.68) v1(11,26.08) v1(11.1,40.78) v1(11.4,0.58) v1(11.5,69.9) v1(11.9,55.38) v1(12.7,33.78) v1(12.7,26.08) v1(12.8,42.48) v1(12.8,38.88) v1(12.8,36.28) v1(12.8,31.28) v1(12.8,28.68) v1(12.8,0.58) v1(12.9,69.9) v1(13.2,54.38) v1(13.7,39.68) v1(13.7,36.28) v1(14.1,0.58) v1(14.3,69.9) v1(14.4,53.38) v1(14.4,38.78) v1(14.6,44.28) v1(14.6,2.08) v1(14.7,36.28) v1(14.7,33.98) v1(14.7,26.18) v1(14.8,28.58) v1(15,40.48) v1(15.3,54.98) v1(15.3,0.58) v1(15.4,67.1) v1(15.4,65.7) v1(15.5,64.38) v1(15.5,2.98) v1(15.6,69.9) v1(16,1.58) v1(16.5,3.08) v1(16.6,47.08) v1(16.7,0.58) v1(16.8,69.9) v1(16.8,68.5) v1(16.8,65.7) v1(16.8,64.3) v1(16.8,62.9) v1(16.8,4.28) v1(17.1,61.38) v1(17.1,59.38) v1(17.6,5.18) v1(17.7,60.48) v1(17.7,58.68) v1(18.1,0.58) v1(18.2,69.9) v1(18.2,68.5) v1(18.2,67.1) v1(18.2,64.3) v1(18.2,62.9) v1(18.3,7.58) v1(18.4,10.08) v1(18.4,9.08) v1(18.8,61.48) v1(18.9,59.78) v1(19.4,12.88) v1(19.5,58.28) v1(19.5,52.48) v1(19.5,51.28) v1(19.5,0.58) v1(19.6,69.9) v1(19.6,68.5) v1(19.6,67.1) v1(19.6,65.7) v1(19.6,62.9) v1(19.8,31.68) v1(19.9,33.78) v1(19.9,29.48) v1(19.9,28.18) v1(20,60.88) v1(20,9.68) v1(20.5,40.68) v1(20.7,52.48) v1(20.7,51.28) v1(20.8,59.58) v1(20.9,46.78) v1(20.9,14.38) v1(20.9,0.58) v1(21,69.9) v1(21,68.5) v1(21,67.1) v1(21,65.7) v1(21,64.3) v1(21.1,61.98) v1(21.1,3.58) v1(21.2,19.48) v1(21.2,15.88) v1(21.2,7.48) v1(21.6,54.18) v1(21.72,9.23) v1(21.8,10.08) v1(21.9,58.18) v1(21.9,56.98) v1(21.9,46.78) v1(22,13.28) v1(22.1,60.88) v1(22.1,59.58) v1(22.2,38.78) v1(22.3,0.58) v1(22.4,69.9) v1(22.4,68.5) v1(22.4,67.1) v1(22.4,65.7) v1(22.4,64.3) v1(22.4,5.88) v1(22.5,54.18) v1(22.5,20.78) v1(22.6,62.28) v1(22.6,14.68) v1(22.9,46.78) v1(23.3,66.08) v1(23.3,26.08) v1(23.3,4.78) v1(23.5,33.88) v1(23.5,32.28) v1(23.5,30.78) v1(23.7,47.48) v1(23.7,0.58) v1(23.8,69.9) v1(23.8,7.58) v1(24,59.58) v1(24.1,62.28) v1(24.1,29.48) v1(24.2,20.48) v1(24.3,57.48) v1(24.8,5.58) v1(25.1,52.58) v1(25.1,51.08) v1(25.1,49.08) v1(25.1,18.08) v1(25.1,0.58) v1(25.2,69.9) v1(25.2,59.58) v1(25.2,58.08) v1(25.2,55.38) v1(25.2,54.48) v1(25.2,15.78) v1(25.2,14.68) v1(25.2,9.98) v1(25.2,1.88) v1(25.5,13.18) v1(25.6,8.38) v1(26.2,19.38) v1(26.2,3.68) v1(26.3,17.68) v1(26.3,15.78) v1(26.33,9.33) v1(26.33,7.53) v1(26.4,50.98) v1(26.5,59.58) v1(26.5,58.18) v1(26.5,0.58) v1(26.6,69.9) v1(26.7,20.98) v1(26.7,4.78) v1(26.8,55.88) v1(26.9,68.78) v1(26.9,67.55) v1(26.9,66.08) v1(26.9,64.68) v1(27.2,12.08) v1(27.5,23.18) v1(27.5,16.08) v1(27.63,59.58) v1(27.63,58.28) v1(27.6,24.38) v1(27.73,62.98) v1(27.7,17.98) v1(27.79,19.43) v1(27.9,0.58) v1(28,69.9) v1(28.3,21.18) v1(28.5,68.78) v1(28.5,67.45) v1(28.5,65.98) v1(28.5,64.58) v1(28.5,50.78) v1(28.6,6.98) v1(28.7,23.28) v1(28.9,16.88) v1(29.03,61.38) v1(29,19.38) v1(29,13.28) v1(29.1,59.58) v1(29.1,58.28) v1(29.2,62.98) v1(29.3,55.88) v1(29.3,0.58) v1(29.4,69.9) v1(29.4,21.78) v1(29.5,14.78) v1(29.5,5.48) v1(30,55.18) v1(30,20.98) v1(30.2,23.18) v1(30.5,61.38) v1(30.5,59.58) v1(30.5,58.28) v1(30.5,11.38) v1(30.6,62.98) v1(30.6,55.88) v1(30.7,69.9) v1(30.7,68.78) v1(30.7,67.45) v1(30.7,65.98) v1(30.7,64.58) v1(30.7,19.08) v1(30.7,0.58) v1(30.8,14.98) v1(30.9,17.28) v1(31,33.08) v1(31,30.88) v1(31,3.58) v1(31.1,28.58) v1(31.1,22.28) v1(31.3,8.98) v1(31.3,7.58) v1(31.9,69.9) v1(31.9,61.38) v1(31.9,59.68) v1(31.9,58.88) v1(31.9,58.18) v1(32.1,17.68) v1(32.1,16.08) v1(32.1,0.58) v1(32.2,23.28) v1(32.2,19.48) v1(32.55,13.23) v1(32.9,30.48) v1(33.1,59.68) v1(33.1,58.88) v1(33.1,58.18) v1(33.1,29.28) v1(33.2,63.38) v1(33.19,9.43) v1(33.3,69.85) v1(33.5,0.58) v1(33.7,39.78) v1(33.69,6.53) v1(33.77,34.21) v1(34,21.58) v1(34.05,7.93) v1(34.2,64.28) v1(34.2,62.18) v1(34.2,59.68) v1(34.2,58.88) v1(34.2,58.18) v1(34.4,31.08) v1(34.4,28.08) v1(34.4,3.48) v1(34.5,65.48) v1(34.6,29.38) v1(34.7,69.85) v1(34.7,68.38) v1(34.7,66.98) v1(34.9,0.58) v1(35.3,64.48) v1(35.4,66.38) v1(35.5,63.08) v1(35.5,62.18) v1(35.5,61.18) v1(35.5,59.68) v1(35.5,58.88) v1(35.5,58.18) v1(35.69,4.33) v1(35.8,29.48) v1(35.8,28.18) v1(35.9,35.08) v1(35.9,34.18) v1(35.9,31.08) v1(36,65.48) v1(36.1,69.85) v1(36.1,68.45) v1(36.1,67.05) v1(36.05,11.83) v1(36.3,64.28) v1(36.3,0.58) v1(36.4,5.98) v1(36.6,59.68) v1(36.6,58.98) v1(36.6,58.28) v1(36.8,63.18) v1(36.8,62.48) v1(36.8,61.68) v1(36.8,61.08) v1(36.8,7.38) v1(37.1,65.88) v1(37.25,11.83) v1(37.5,65.18) v1(37.5,64.48) v1(37.5,59.68) v1(37.5,58.98) v1(37.53,58.21) v1(37.6,63.78) v1(37.6,63.08) v1(37.6,62.38) v1(37.6,61.68) v1(37.6,61.08) v1(37.7,0.58) v1(37.8,23.38) v1(38,30.58) v1(38,29.48) v1(38.1,28.38) v1(38.2,65.88) v1(38.3,53.08) v1(38.4,65.18) v1(38.4,64.48) v1(38.4,63.78) v1(38.43,63.08) v1(38.43,62.41) v1(38.43,61.71) v1(38.4,61.08) v1(38.4,59.68) v1(38.4,58.98) v1(38.43,58.21) v1(38.4,6.28) v1(38.49,9.43) v1(38.69,7.43) v1(38.8,4.98) v1(38.9,21.98) v1(38.9,3.68) v1(39,32.98) v1(39.1,23.28) v1(39.1,11.98) v1(39.1,0.58) v1(39.3,30.08) v1(39.4,34.08) v1(39.6,37.58) v1(39.7,34.88) v1(40.1,39.18) v1(40.33,48.28) v1(40.3,13.28) v1(40.4,22.18) v1(40.4,0.58) v1(40.5,28.48) v1(40.45,11.63) v1(40.5,7.38) v1(40.59,19.33) v1(40.7,37.68) v1(40.7,34.78) v1(40.7,32.98) v1(40.7,23.38) v1(40.7,5.88) v1(40.75,16.93) v1(40.9,29.28) v1(41.1,15.68) v1(41.1,14.38) v1(41.3,21.68) v1(41.6,46.98) v1(41.6,20.48) v1(41.6,13.28) v1(41.6,0.58) v1(41.8,48.28) v1(41.9,65.78) v1(41.93,64.41) v1(41.93,63.51) v1(41.93,62.41) v1(41.93,61.71) v1(41.93,61.11) v1(41.9,27.18) v1(41.9,11.58) v1(42.1,59.58) v1(42.1,58.58) v1(42.2,28.58) v1(42.3,30.08) v1(42.4,4.98) v1(42.45,12.93) v1(42.5,7.48) v1(42.6,23.38) v1(42.69,19.33) v1(42.69,17.03) v1(42.7,15.08) v1(42.9,50.88) v1(42.9,49.88) v1(42.93,48.26) v1(42.9,46.98) v1(43,0.58) v1(43.1,59.58) v1(43.1,27.88) v1(43.2,65.78) v1(43.2,22.18) v1(43.2,11.68) v1(43.3,28.98) v1(43.6,21.18) v1(43.7,13.98) v1(43.7,3.48) v1(43.8,27.18) v1(43.94,16.68) v1(43.9,12.63) v1(44.2,23.18) v1(44.2,8.08) v1(44.3,48.28) v1(44.3,27.98) v1(44.3,9.88) v1(44.4,65.78) v1(44.4,46.98) v1(44.4,0.58) v1(44.5,69.85) v1(44.5,68.45) v1(44.5,67.05) v1(44.5,52.28) v1(44.6,18.58) v1(44.8,14.48) v1(45.1,15.68) v1(45.2,27.18) v1(45.53,50.88) v1(45.5,49.88) v1(45.53,48.28) v1(45.72,65.85) v1(45.7,21.48) v1(45.7,8.68) v1(45.7,6.53) v1(45.8,0.58) v1(45.9,69.85) v1(45.9,68.45) v1(45.9,67.05) v1(46.1,13.08) v1(46.8,32.88) v1(46.92,65.85) v1(47.2,21.48) v1(47.24,8.23) v1(47.2,0.58) v1(47.3,69.85) v1(47.3,68.45) v1(47.3,67.05) v1(47.3,59.08) v1(47.3,9.98) v1(47.7,59.88) v1(47.7,3.18) v1(48,43.38) v1(48,42.48) v1(48.04,4.53) v1(48.6,5.78) v1(48.6,0.58) v1(48.7,69.85) v1(48.7,68.45) v1(48.7,67.05) v1(48.8,60.68) v1(48.9,61.88) v1(49,64.28) v1(49,63.18) v1(49.24,7.73) v1(49.4,65.78) v1(49.5,11.68) v1(49.8,6.58) v1(50,0.58) v1(50.1,69.85) v1(50.1,68.45) v1(50.1,67.05) v1(50.3,56.98) v1(50.3,4.78) v1(50.4,64.58) v1(50.4,62.78) v1(50.4,43.48) v1(50.4,42.38) v1(50.7,22.78) v1(51.2,21.08) v1(51.2,9.78) v1(51.3,65.78) v1(51.4,42.38) v1(51.44,8.63) v1(51.4,0.58) v1(51.5,69.85) v1(51.5,68.45) v1(51.5,67.05) v1(51.7,4.98) v1(51.8,56.98) v1(52,63.38) v1(52.1,1.23) v1(52.2,22.08) v1(52.3,64.58) v1(52.3,6.88) v1(52.6,61.88) v1(52.7,11.68) v1(52.8,0.58) v1(52.9,69.85) v1(52.9,68.45) v1(52.9,67.05) v1(53,5.18) v1(53.1,65.78) v1(53.1,21.08) v1(53.2,19.88) v1(53.2,18.76) v1(53.2,16.58) v1(53.2,14.78) v1(53.3,58.98) v1(53.4,12.98) v1(53.5,62.58) v1(53.6,44.68) v1(53.7,43.18) v1(53.9,8.28) v1(54,63.38) v1(54.1,64.58) v1(54.2,0.58) v1(54.3,69.85) v1(54.3,68.45) v1(54.3,67.05) v1(54.4,11.98) v1(54.5,58.98) v1(54.6,6.58) v1(54.8,65.78) v1(54.8,61.88) v1(55,60.38) v1(55,44.68) v1(55,5.18) v1(55.1,43.18) v1(55.2,62.68) v1(55.4,11.48) v1(55.5,64.28) v1(55.6,0.58) v1(55.7,69.85) v1(55.7,68.45) v1(55.7,67.05) v1(55.8,52.38) v1(55.9,61.88) v1(55.9,60.38) v1(56,54.68) v1(56.1,48.88) v1(56.1,46.38) v1(56.2,47.78) v1(56.2,29.28) v1(56.2,8.28) v1(56.3,58.98) v1(56.4,65.48) v1(56.4,44.68) v1(56.5,43.18) v1(56.6,66.38) v1(56.6,4.58) v1(56.7,15.88) v1(56.8,63.28) v1(57,0.58) v1(57.1,69.9) v1(57.1,68.5) v1(57.1,67.1) v1(57.1,61.98) v1(57.3,64.68) v1(57.4,60.38) v1(57.4,38.08) v1(57.5,48.08) v1(57.5,14.88) v1(57.8,43.18) v1(57.9,44.68) v1(57.9,40.68) v1(57.9,29.28) v1(58,62.58) v1(58,3.08) v1(58.1,65.78) v1(58.3,69.9) v1(58.3,68.5) v1(58.3,67.1) v1(58.4,49.08) v1(58.4,0.58) v1(58.6,47.08) v1(58.6,14.08) v1(58.6,1.88) v1(58.8,63.98) v1(58.9,42.08) v1(58.9,40.68) v1(58.9,19.18) v1(59,61.98) v1(59,48.48) v1(59,44.68) v1(59,43.18) v1(59.4,65.58) v1(59.6,69.9) v1(59.6,68.5) v1(59.6,67.1) v1(59.8,0.58) v1(60,54.08) v1(60.3,56.48) v1(60.7,3.28) v1(60.8,8.38) v1(60.8,5.88) v1(61,69.9) v1(61,68.5) v1(61,67.1) v1(61,64.18) v1(61.2,0.58) v1(61.3,51.58) v1(61.5,54.08) v1(61.8,65.58) v1(62.4,69.9) v1(62.4,68.5) v1(62.4,67.1) v1(62.6,0.58) v1(62.7,16.58) v1(62.7,14.68) v1(62.8,56.48) v1(62.8,54.18) v1(62.8,37.48) v1(62.8,32.98) v1(62.8,22.78) v1(62.8,21.58) v1(62.8,20.08) v1(62.8,11.58) v1(62.9,52.98) v1(62.9,43.18) v1(62.9,42.18) v1(62.9,40.68) v1(63,65.58) v1(63,60.58) v1(63,58.38) v1(63,51.58) v1(63,49.08) v1(63,46.48) v1(63,44.78) v1(63.1,30.58) v1(63.1,29.18) v1(63.1,27.18) v1(63.1,25.38) v1(63.2,12.68) v1(63.2,8.28) v1(63.3,6.58) v1(63.3,4.38) v1(63.8,69.9) v1(63.8,68.5) v1(63.8,67.1) v1(63.8,55.48) v1(63.8,15.18) v1(63.9,64.18) v1(63.9,2.88) v1(64,60.58) v1(64,0.58) v1(64.1,62.38) v1(64.1,17.88) v1(64.4,37.48) v1(64.6,53.38) v1(64.6,11.48) v1(64.7,44.88) v1(64.7,29.28) v1(64.7,4.38) v1(64.8,58.38) v1(64.8,54.58) v1(64.8,52.08) v1(64.8,50.28) v1(64.8,48.98) v1(64.8,47.68) v1(64.8,46.48) v1(64.8,43.08) v1(64.8,42.18) v1(64.8,30.58) v1(64.8,27.78) v1(64.8,26.88) v1(64.9,24.78) v1(65,35.78) v1(65,22.38) v1(65.1,40.68) v1(65.1,17.08) v1(65.1,14.58) v1(65.1,12.08) v1(65.2,69.9) v1(65.2,68.5) v1(65.2,67.1) v1(65.3,19.28) v1(65.4,0.58) v1(65.6,65.48) v1(66.3,61.78) v1(66.3,46.48) v1(66.4,59.08) v1(66.4,56.58) v1(66.6,69.9) v1(66.6,68.5) v1(66.6,67.1) v1(66.7,0.58) v1(67,8.38) v1(67,5.78) v1(67.1,20.98) v1(67.1,3.28) v1(67.2,18.48) v1(67.2,15.98) v1(67.2,13.38) v1(67.3,64.18) v1(67.8,59.08) v1(67.9,65.58) v1(67.9,0.58) v1(68,69.9) v1(68,67.1) v1(68,48.98) v1(68,33.78) v1(68,31.18) v1(68,26.08) v1(68.1,36.28) v1(68.1,28.68) v1(68.7,18.48) v1(68.7,15.98) v1(68.7,13.38) v1(68.8,44.68) v1(68.8,42.68) v1(68.8,23.58) v1(68.8,21.08) v1(69,10.28) v1(69.1,56.58) v1(69.3,7.68) v1(69.3,0.58) v1(69.4,69.9) v1(69.7,26.58) v1(69.7,25.48) v1(69.7,23.58) v1(69.7,17.28) v1(69.8,65.38) v1(69.8,49.48) v1(69.8,20.98) v1(69.8,19.28) v1(70.1,11.58) v1(70.2,2.68) v1(70.3,63.18) v1(70.3,61.58) v1(70.3,60.31) v1(70.3,54.68) v1(70.3,5.88) v1(70.7,28.88) v1(70.7,0.58) v1(70.8,69.9) v1(71.2,12.68) v1(71.2,3.58) v1(71.3,43.08) v1(71.4,60.28) v1(71.4,38.78) v1(71.4,36.98) v1(71.5,53.38) v1(71.5,49.58) v1(71.5,47.88) v1(71.5,46.28) v1(71.5,44.68) v1(71.5,32.18) v1(71.5,30.48) v1(71.5,28.88) v1(71.6,26.68) v1(71.6,24.38) v1(71.6,19.58) v1(71.6,17.58) v1(71.7,58.08) v1(71.9,21.98) v1(71.9,10.28) v1(72.1,0.58) v1(72.2,7.78) v1(72.4,56.58) v1(72.7,51.78) v1(73.1,69.85) v1(73.1,68.45) v1(73.1,67.05) v1(73.1,4.48) v1(73.2,54.98) v1(73.4,25.68) v1(73.5,0.58) v1(73.6,9.98) v1(73.6,7.88) v1(73.7,14.98) v1(73.7,5.78) v1(74.1,52.3) v1(74.1,50.7) v1(74.2,12.28) v1(74.4,69.85) v1(74.4,68.45) v1(74.4,67.05) v1(74.4,65.65) v1(74.4,64.25) v1(74.4,62.85) v1(74.4,61.45) v1(74.4,60.25) v1(74.5,2.68) v1(74.6,21.98) v1(74.6,18.58) v1(74.8,25.68) v1(74.9,58.08) v1(74.9,9.98) v1(74.9,7.88) v1(74.9,0.58) v1(75,55.08) v1(75,29.47) v1(75,24.08) v1(75,5.78) v1(75.1,56.68) v1(75.1,27.18) v1(75.3,4.28) v1(75.6,14.98) v1(75.6,12.28) v1(75.8,69.85) v1(75.8,68.45) v1(75.8,67.05) v1(75.9,60.25) v1(76,25.68) v1(76.3,9.98) v1(76.3,7.88) v1(76.3,0.58) v1(76.4,5.78) v1(76.4,2.58) v1(76.7,4.28) v1(76.8,21.98) v1(76.8,16.88) v1(76.8,12.28) v1(76.9,41.26) v1(76.9,19.98) v1(77.2,69.85) v1(77.2,68.45) v1(77.2,67.05) v1(77.4,60.25) v1(77.4,25.68) v1(77.6,23.98) v1(77.6,14.98) v1(77.7,0.58) v1(77.8,41.26) v1(77.8,9.98) v1(77.8,7.88) v1(77.9,5.78) v1(77.9,4.28) v1(78.1,27.08) v1(78.2,12.28) v1(78.5,2.68) v1(78.6,69.85) v1(78.9,49.48) v1(78.9,45.58) v1(79,60.25) v1(79,9.98) v1(79,7.88) v1(79.1,68.45) v1(79.1,67.05) v1(79.1,5.78) v1(79.1,0.58) v1(79.3,19.58) v1(79.3,17.28) v1(79.3,4.28) v1(79.4,14.88) v1(79.5,26.68) v1(79.5,24.38) v1(79.8,35.67) v1(79.9,33.47) v1(80.1,69.58) v1(80.3,49.48) v1(80.3,48.08) v1(80.3,46.88) v1(80.3,45.48) v1(80.5,68.45) v1(80.5,67.05) v1(80.5,60.25) v1(80.5,21.98) v1(80.5,0.58) v1(80.7,19.58) v1(80.7,17.18) v1(80.7,7.78) v1(80.8,50.76) v1(80.8,44.16) v1(80.8,41.26) v1(80.8,38.23) v1(80.8,31.73) v1(80.8,2.98) v1(80.9,14.88) v1(80.9,5.48) v1(81.7,50.76) v1(81.7,44.16) v1(81.7,41.26) v1(81.7,38.23) v1(81.7,31.73) v1(81.8,68.45) v1(81.8,67.05) v1(81.8,49.48) v1(81.8,48.08) v1(81.8,46.88) v1(81.8,45.48) v1(81.9,60.25) v1(81.9,58.75) v1(81.9,57.25) v1(81.9,55.65) v1(81.9,54.15) v1(81.9,35.68) v1(81.9,33.48) v1(82.05,28.48) v1(82.05,26.78) v1(82.05,25.08) v1(82.05,23.38) v1(82.05,21.68) v1(82.05,19.98) v1(82.05,18.28) v1(82.05,16.58) v1(82.05,14.88) v1(82.05,13.18) v1(82.05,11.48) v1(82.05,9.78) v1(82.05,8.08) v1(82.05,6.38) v1(82.05,4.68) v1(82.05,2.98) v1(82,0.88)
V3: length 12.6
  TOP w0.2: C23.1 16.92,52.11 U1.6 ; U1.1 C20.1 v1(21.6,55.01)
  TOP w0.4: v1(16.55,51.23) 16.9,51.58 C23.1
  POWER w0.5: v1(21.6,55.01) 19.23,55.01 16.55,52.33 v1(16.55,51.23)
VDD_DMIC: length 43.9
  TOP w0.5: v1(50.82,36.37) 50.83,36.35 C32.1 U4.6 ; R29.1 20.25,34.68 19.75,35.18 v1(19.75,35.68) C31.1 U3.6 21.97,37.18 22.66,37.18 U3.2
  POWER w0.5: v1(50.82,36.37) 48.7,38.48 39.8,38.48 37.7,40.58 26.1,40.58 21.2,35.68 v1(19.75,35.68)
32K_XC1: length 57.6
  TOP w0.2: v1(43,55.58) 43,54.88 42.4,54.28 U2.62 ; J8.10 7,27.38 9.9,30.28 9.9,38.08 17.1,45.28 23.9,45.28 30,51.38 v1(30,52.98)
  POWER w0.2: v1(43,55.58) 42.5,55.08 41.1,55.08 40.3,55.88 32.9,55.88 v1(30,52.98)
  BOTTOM w0.2: v1(30,52.98) R6.2
32K_XC2: length 62.5
  TOP w0.2: v1(30,54.12) 30,54.08 30.6,53.48 30.6,51.38 24.14,44.92 17.25,44.92 10.26,37.93 10.26,27.94 7.16,24.84 J8.12 ; v1(43,56.68) 42.5,56.18 42.5,54.98 42.05,54.53 U2.63
  POWER w0.2: v1(43,56.68) 42.3,56.68 41.9,56.28 32.16,56.28 v1(30,54.12)
  BOTTOM w0.2: v1(30,54.12) R7.2
AIN_LINEIN_N: length 21.4
  TOP w0.2: J8.7 v1(14.7,29.92) ; C45.2 v1(23.43,14.7)
  BOTTOM w0.2: v1(23.43,14.7) 17.6,20.53 17.6,27.02 v1(14.7,29.92)
AIN_LINEIN_P: length 26.9
  TOP w0.2: C46.2 v1(24.43,14.68) ; J8.3 v1(14.7,35)
  BOTTOM w0.2: v1(14.7,35) 18.7,31 18.7,23.28 24.43,17.55 v1(24.43,14.68)
AIN_MIC_N: length 19.1
  TOP w0.2: J8.5 v1(14.7,32.46)
  TOP w0.3: C38.2 v1(21.22,18.68)
  BOTTOM w0.2: v1(14.7,32.46) 18.1,29.06 18.1,21.8 v1(21.22,18.68)
AIN_MIC_P: length 22.4
  TOP w0.2: J8.1 v1(14.7,37.54) ; C36.2 v1(22.5,21.63)
  BOTTOM w0.2: v1(22.5,21.63) 21.35,21.63 19.2,23.78 19.2,33.04 v1(14.7,37.54)
BL_3V3: length 38.5
  POWER w0.5: v1(65.12,37.54) 67.3,35.36 67.3,23.08 62,17.78 v1(53.2,17.78)
  BOTTOM w0.5: v1(53.2,17.78) 51.64,16.22 J12.9 ; J13.2 v1(65.12,37.54)
BL_5V: length 70.3
  BOTTOM w0.5: J14.3 7.08,35 9.9,32.18 9.9,9.38 10.9,8.38 21.8,8.38 23.4,6.78 27.4,6.78 31.3,10.68 46,10.68 J12.10
DM0: length 4.7
  TOP w0.2: R27.1 74.52,35.18 J6.A7 77.07,35.18 77.27,34.98 77.27,34.38 77.07,34.18 J6.B7
DM1: length 4.4
  TOP w0.2: v1(75.1,47.75) J5.A7 ; R19.1 74.52,46.75 v1(75.1,46.75) J5.B7
  BOTTOM w0.2: v1(75.1,47.75) v1(75.1,46.75)
DM2: length 10.8
  TOP w0.2: U1.8 18.03,51.11 16.2,49.28 13.72,49.28 D9.2 13.53,49.23 J4.A7 10.53,49.23 10.33,49.43 10.33,50.03 10.53,50.23 J4.B7
DMICCK: length 60.4
  TOP w0.2: J7.25 66.52,32.46 65,33.98 58.2,33.98 57.3,33.08 v1(52.5,33.08) ; v1(51.5,40.28) R24.2 U4.4 ; v1(19.75,40.33) R23.2 U3.4
  BOTTOM w0.2: v1(52.5,33.08) 52.5,39.28 v1(51.5,40.28) 50.7,41.08 26.3,41.08 24.7,39.48 20.6,39.48 v1(19.75,40.33)
DMICDAT: length 54.6
  TOP w0.2: U4.5 51.9,38 v1(51.89,37.99) ; v1(51.9,34.18) 56.7,34.18 58.8,36.28 65.3,36.28 66.58,35 J7.23 ; U3.5 v1(22.2,38)
  BOTTOM w0.2: 51.9,38 51.9,38.58 50,40.48 26.5,40.48 24.02,38 v1(22.2,38) ; 51.9,38 v1(51.89,37.99) ; 51.9,38 v1(51.9,34.18)
DP0: length 4.3
  TOP w0.2: v1(75.2,35.68) J6.B6 ; R28.1 74.52,34.68 v1(75.2,34.68) J6.A6
  BOTTOM w0.2: v1(75.2,35.68) v1(75.2,34.68)
DP1: length 4.7
  TOP w0.2: R17.1 74.52,47.25 J5.A6 77.07,47.25 77.27,47.45 77.27,48.05 77.07,48.25 J5.B6
DP2: length 10.5
  TOP w0.2: J4.A6 v1(12.4,49.73) 13.52,49.73 D8.2 13.73,49.68 16,49.68 17.93,51.61 U1.7 ; v1(12.41,48.73) J4.B6
  BOTTOM w0.2: v1(12.4,49.73) 12.4,48.74 v1(12.41,48.73)
EXT_3V3: length 87.2
  TOP w0.5: R30.2 v1(23.4,34.68)
  POWER w0.5: v1(23.4,34.68) 23.4,35.38 24.8,36.78 40.1,36.78 42,34.88 56.77,34.88 v1(58.47,33.18)
  BOTTOM w0.5: v1(23.4,34.68) 19.7,34.68 13.5,40.88 13.5,50.28 9.8,53.98 9.8,63.95 10.89,65.04 J3.7 ; J13.4 66.62,35 65.4,33.78 59.07,33.78 v1(58.47,33.18)
LED_B: length 9.5
  TOP w0.4: J7.7 70.04,55.32 72.1,57.38 R9.1
LED_G: length 10.3
  TOP w0.4: R12.1 73.9,54.38 69.76,50.24 J7.11
LED_R: length 9
  TOP w0.4: J7.5 70.38,57.86 71.4,58.88 R8.1
LED_W: length 9.9
  TOP w0.4: R10.1 72.8,55.88 69.7,52.78 J7.9
TL_3V3C: length 87
  TOP w0.5: R4.2 v1(69,59.08) ; U6.5 20.75,31.33 C34.1 R29.2 R30.1 v1(23.5,33.08)
  POWER w0.5: v1(23.5,33.08) 24.3,33.08 27,35.78 37.1,35.78 38,34.88 38,31.58 38.6,30.98 59.7,30.98 63.6,34.88 63.6,37.78 67.2,41.38 67.2,57.28 v1(69,59.08)
TL_5V: length 152.9
  TOP w0.2: L3.2 v1(18.93,56.78)
  TOP w0.4: U6.3 22.65,28.13 22.3,28.48 21.1,28.48 20.75,28.13 U6.1
  TOP w0.5: U6.1 20.75,25.63 C35.1 v1(20.15,24.73) ; R18.1 14.3,45.88 v1(12.4,43.98) ; R21.1 R22.2 72.1,42.6 71.6,42.1 71.6,40.07 v1(73.3,38.37) R25.1
  POWER w0.5: v1(73.3,38.37) 73.3,27.38 70.5,24.58 70.5,13.08 68.1,10.68 23.6,10.68 20.15,14.13 v1(20.15,24.73) 20.15,26.63 15.45,31.33 14.15,31.33 8.38,37.1 v1(8.38,37.54) 8.38,39.96 v1(12.4,43.98) 15.7,47.28 15.7,53.55 v1(18.93,56.78)
  BOTTOM w0.5: J14.1 v1(8.38,37.54)
TL_AVDD1P2: length 10.4
  TOP w0.2: U2.47 48.86,51.94 49,52.08
  TOP w0.3: 49,52.08 50.4,53.48
  TOP w0.35: 50.4,53.48 50.4,54.94 C18.1
  TOP w0.4: AVDD1P2.1 52.9,56.28 51.74,56.28 C18.1
  TOP w0.5: R40.2 AVDD1P2.1
TL_AVDD3: length 6.3
  TOP w0.2: 44.15,54.73 U2.57
  TOP w0.3: C11.1 44.33,54.91 44.15,54.73
  TOP w0.35: AVDD3.1 44.33,57.55 C11.1
  TOP w0.5: AVDD3.1 44.9,58.58 R43.2
TL_DM: length 7.9
  TOP w0.15: R19.2 73.01,46.86 72.83,46.86 D11.2 72.22,46.85 70.37,46.85 69.8,46.28 67.25,46.28 67.1,46.13 J7.15
TL_DP: length 7.8
  TOP w0.15: J7.13 67.1,46.73 67.25,46.58 69.68,46.58 70.25,47.15 72.22,47.15 D10.2 72.81,47.16 73.03,47.16 R17.2
TL_DVDD1P2: length 7.9
  TOP w0.2: U2.46 49.21,51.59 49.5,51.88 49.54,51.88
  TOP w0.35: 49.54,51.88 C21.1 51.3,53.64 51.3,54.08 52.5,55.28 DVDD1P2.1
  TOP w0.5: DVDD1P2.1 52.9,54.98 R39.2
TL_FLASH: length 68.1
  TOP w0.35: v1(56.8,55.08) 56.8,55.58 55.7,56.68 55.7,57.58 54.9,58.38 52.6,58.38 R46.2
  TOP w0.5: C33.1 34.87,32.36 ; C33.1 34.87,34.44 34.37,34.93 U5.8 ; C33.1 34.89,33.47 R31.1 ; 34.87,32.36 35.27,31.96 ; 34.87,32.36 34.47,31.96 ; 35.27,31.96 v1(39,31.96) SW2.2 ; 35.27,31.96 34.47,31.96 ; 34.47,31.96 SW2.1
  POWER w0.5: v1(39,31.96) 59.47,31.96 61.3,33.78 61.3,50.58 v1(56.8,55.08)
TL_IR: length 32.2
  TOP w0.2: v1(47.25,57.08) 46.7,56.53 46.7,55.68 46.45,55.43 C65.1 U2.51
  POWER w0.2: v1(47.25,57.08) 47.25,58.23 50.2,61.18 67,61.18 67.98,62.16 D2.C
TL_KEY1: length 37.9
  TOP w0.2: J7.43 69.22,9.6 72.24,12.62 SW5.1 v1(78.7,13.55) SW5.2 ; SW3.2 v1(78.7,27.75) SW3.1
  BOTTOM w0.2: v1(78.7,27.75) 78.7,13.55 v1(78.7,13.55)
TL_KEY2: length 46.9
  TOP w0.2: 67.68,7.06 71.5,10.88 80.4,10.88 81.5,11.98 81.5,19.78 80.63,20.65 SW4.2 SW4.1 ; 67.68,7.06 67.72,7.06 68.33,6.45 SW6.1 SW6.2 ; 67.68,7.06 J7.45
TL_KEY3: length 50.7
  TOP w0.2: SW4.3 v1(77.6,16.15) SW4.4 ; SW4.3 72.03,16.15 70.8,17.38 70.8,21.98 72.07,23.25 SW3.3 v1(77.62,23.25) SW3.4 ; SW4.3 69.9,13.81 69.9,12.18 68.7,10.98 65.6,10.98 64.4,9.78 64.4,5.78 65.66,4.52 J7.47
  BOTTOM w0.2: v1(77.6,16.15) 77.6,23.23 v1(77.62,23.25)
TL_KEY4: length 29.8
  TOP w0.2: J7.49 72.21,1.98 SW6.3 SW6.4 80.67,1.95 81.5,2.78 81.5,8.28 80.73,9.05 SW5.4 SW5.3
TL_MICBIAS: length 74.5
  TOP w0.5: v1(57.6,41.38) 65.4,41.38 66.64,42.62 J7.17 ; R33.1 v1(26.7,21.63)
  POWER w0.5: v1(57.6,41.38) 41.6,41.38 39.9,43.08 20.6,43.08 18.2,40.68 18.2,34.38 26.7,25.88 v1(26.7,21.63)
TL_MSPICK: length 13
  TOP w0.2: U5.6 31.89,37.47 31.7,37.29 31.7,37.01 31.9,36.8 33.53,36.8 34.5,37.78 34.5,39.18 36.5,41.18 37.8,41.18 39.25,42.63 U2.2
TL_MSPICN: length 29.2
  TOP w0.2: 37.13,34.93 36.83,34.64 v1(36.83,34.18) R31.2 ; 37.13,34.93 35.5,36.56 35.5,39.08 36.8,40.38 38,40.38 39.95,42.33 U2.4 ; 37.13,34.93 U5.1 ; SW2.4 v1(36.8,27.45) SW2.3
  POWER w0.2: v1(36.83,34.18) 36.83,27.49 v1(36.8,27.45)
TL_MSPIIO2: length 11.1
  TOP w0.2: U2.6 40.65,41.83 38.4,39.58 37,39.58 36.3,38.88 36.3,37.05 36.5,36.85 36.87,36.85 37.49,37.47 U5.3
